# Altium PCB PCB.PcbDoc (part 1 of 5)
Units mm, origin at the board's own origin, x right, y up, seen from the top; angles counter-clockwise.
Board outline 101.6 x 53.34 mm, 6 copper layers (Top Layer, Int1 (GND), Int2, Int3, Int4 (GND), Bottom Layer), stack 1.625 mm thick; 228 components, 228 nets, 1016 pads, 995 vias.
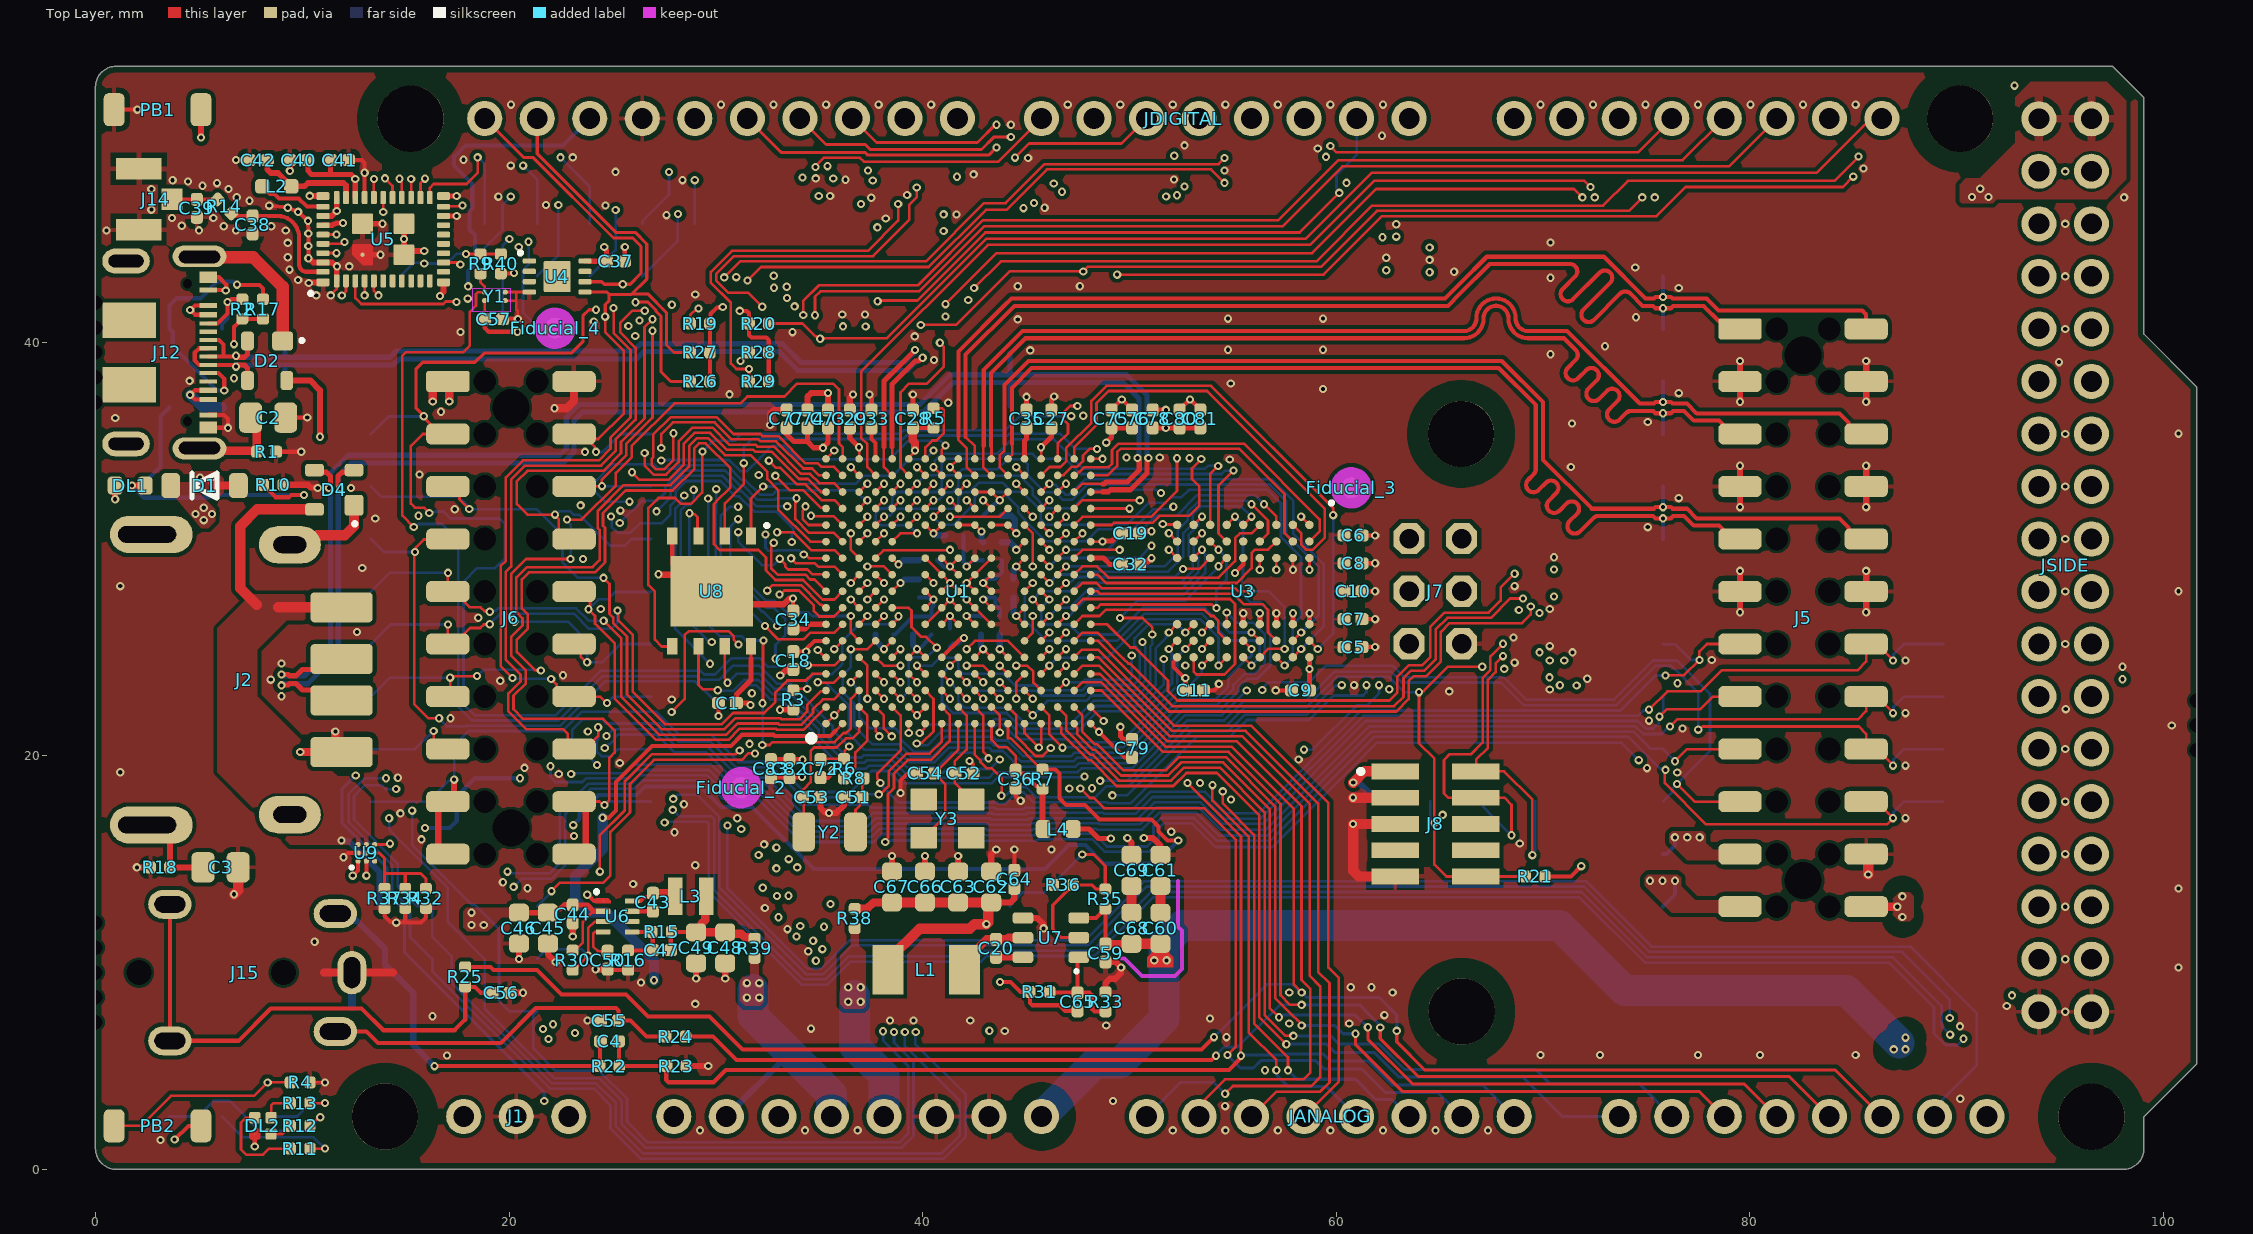
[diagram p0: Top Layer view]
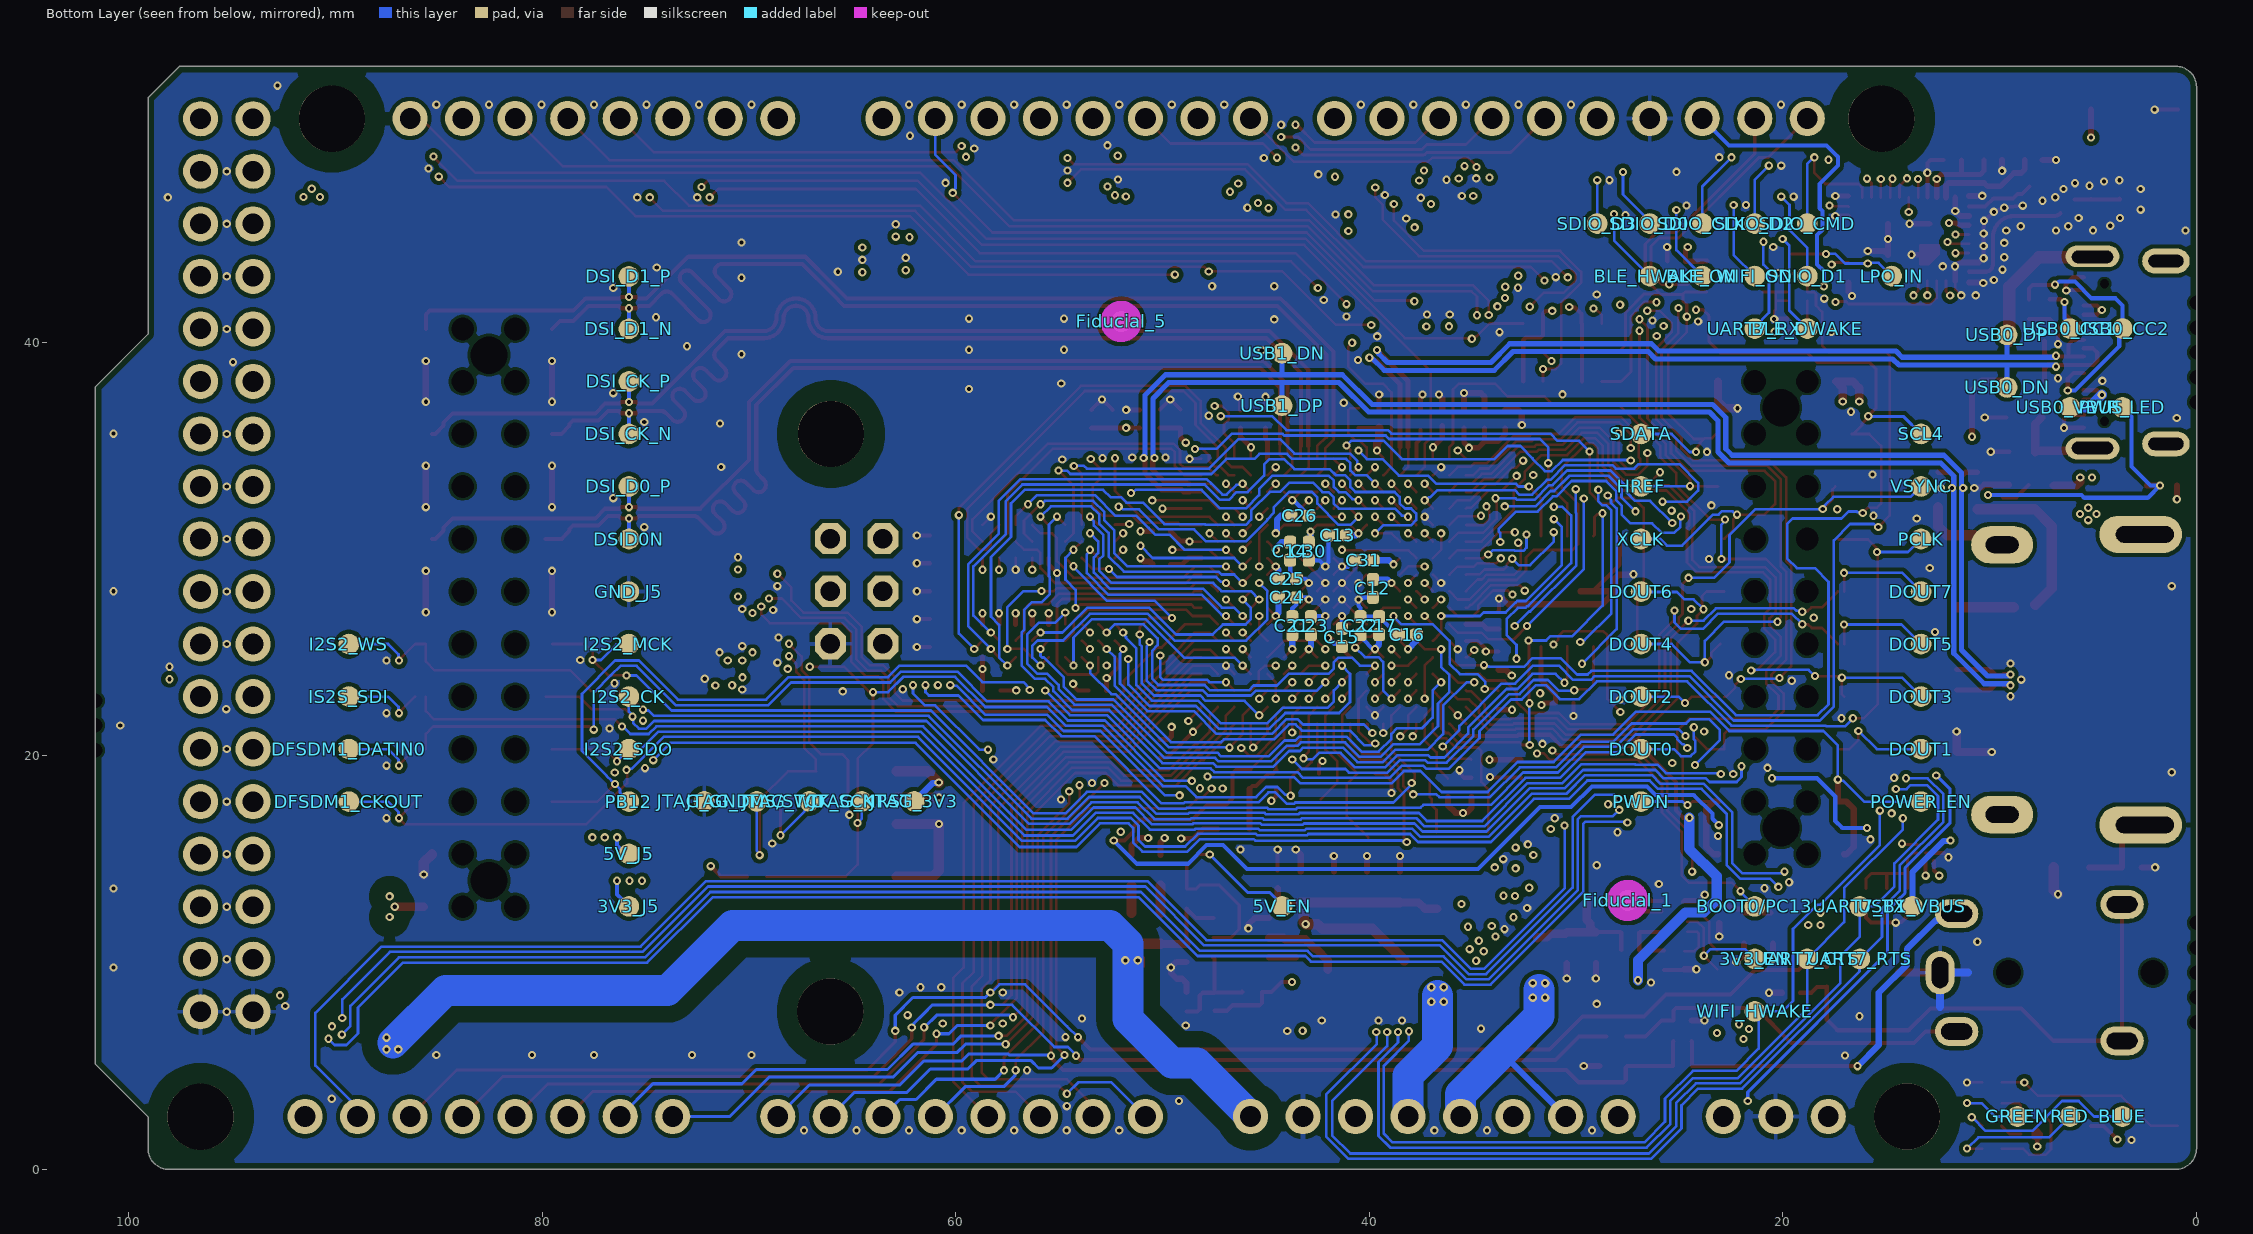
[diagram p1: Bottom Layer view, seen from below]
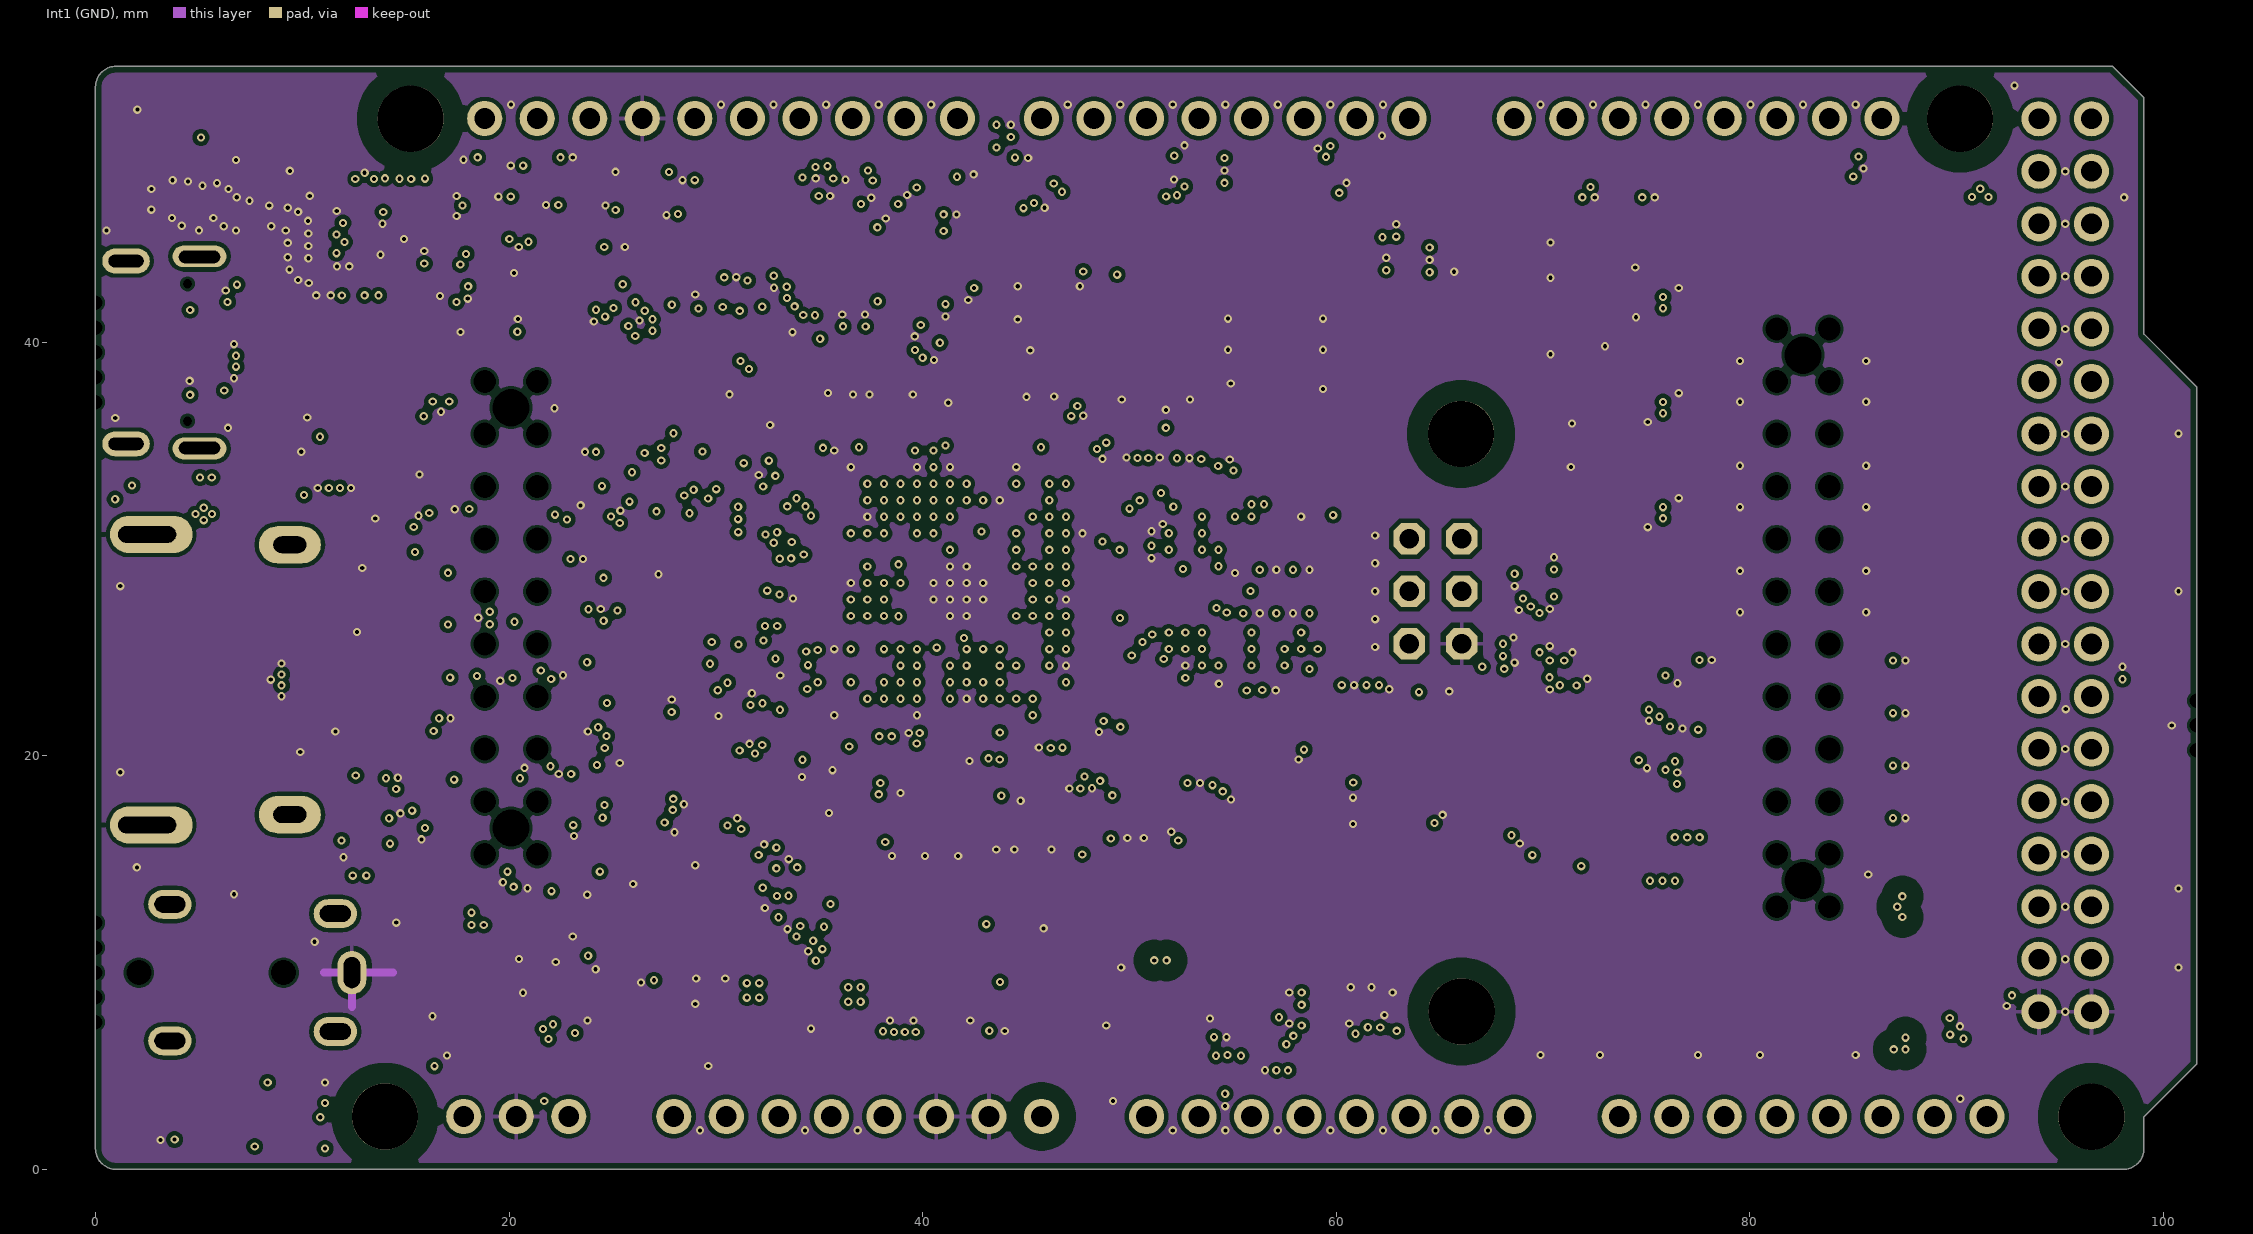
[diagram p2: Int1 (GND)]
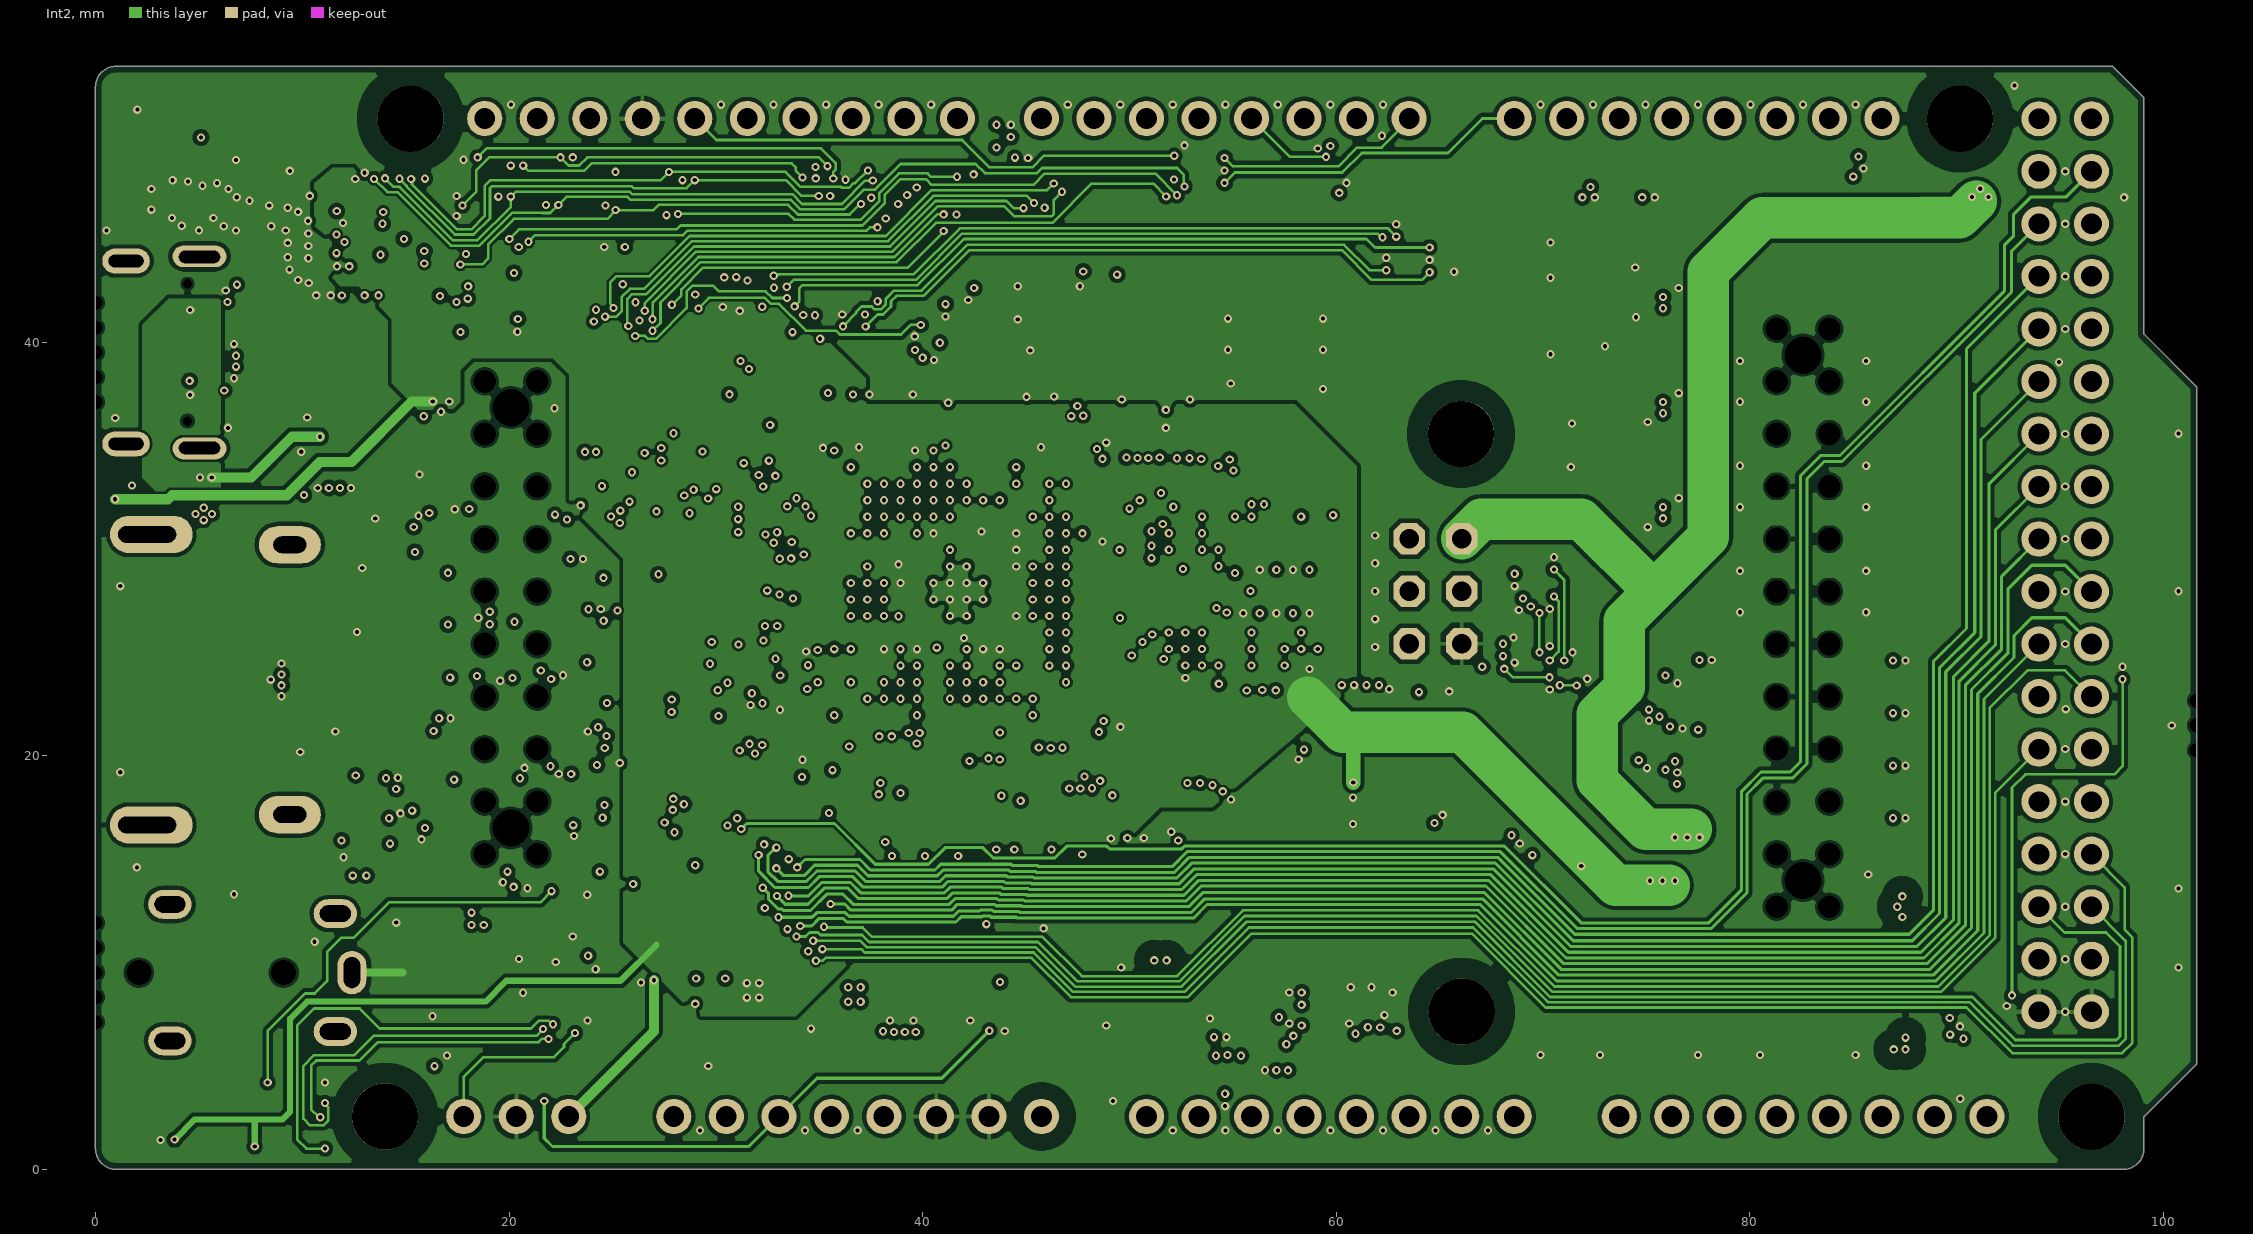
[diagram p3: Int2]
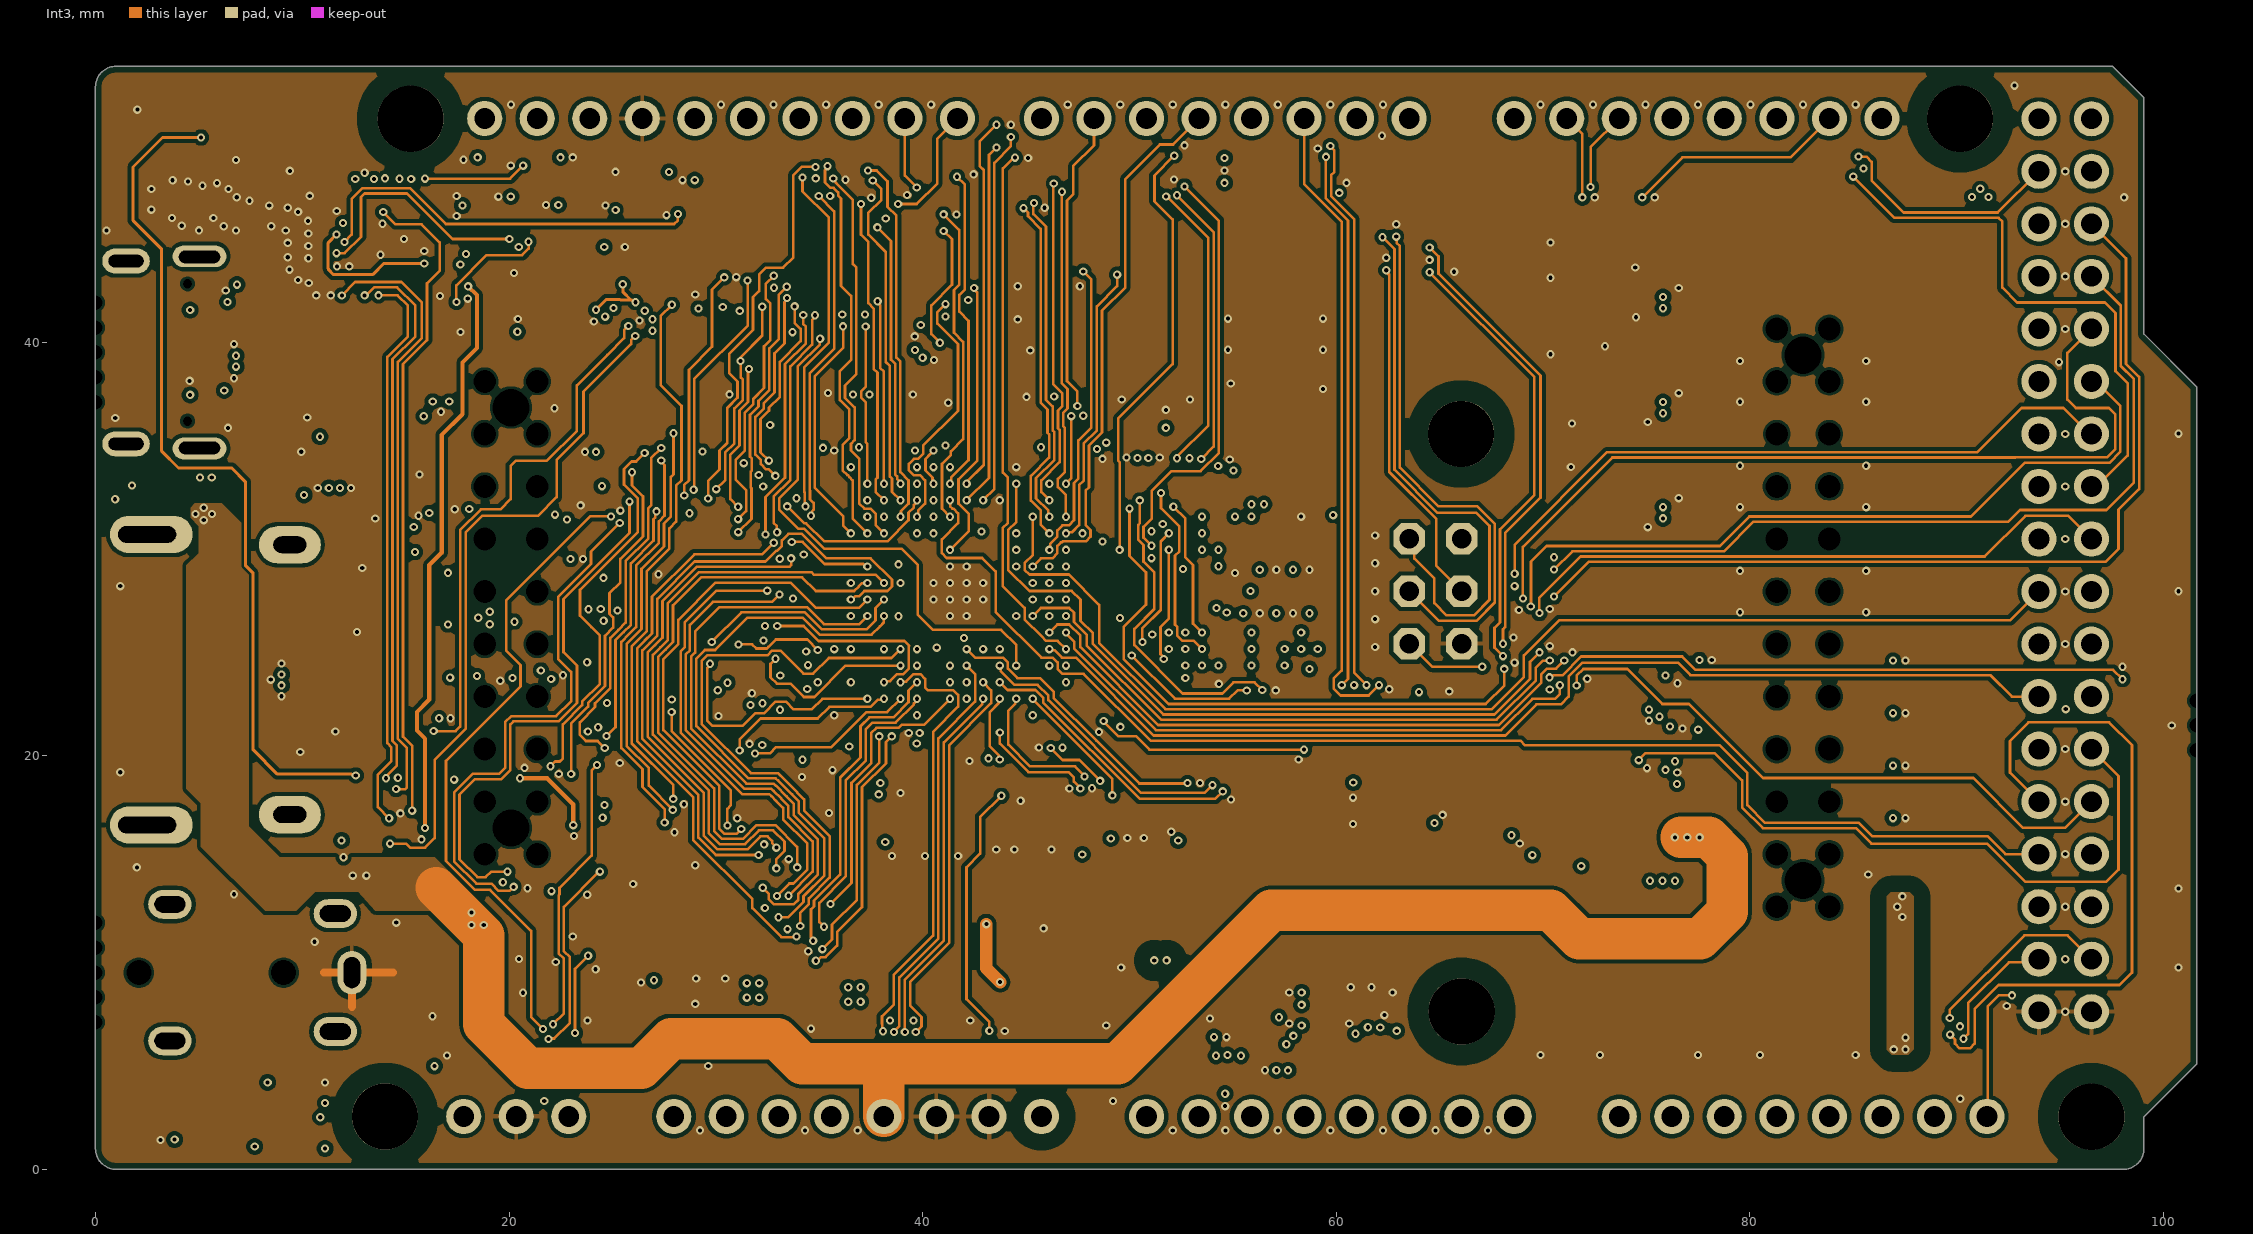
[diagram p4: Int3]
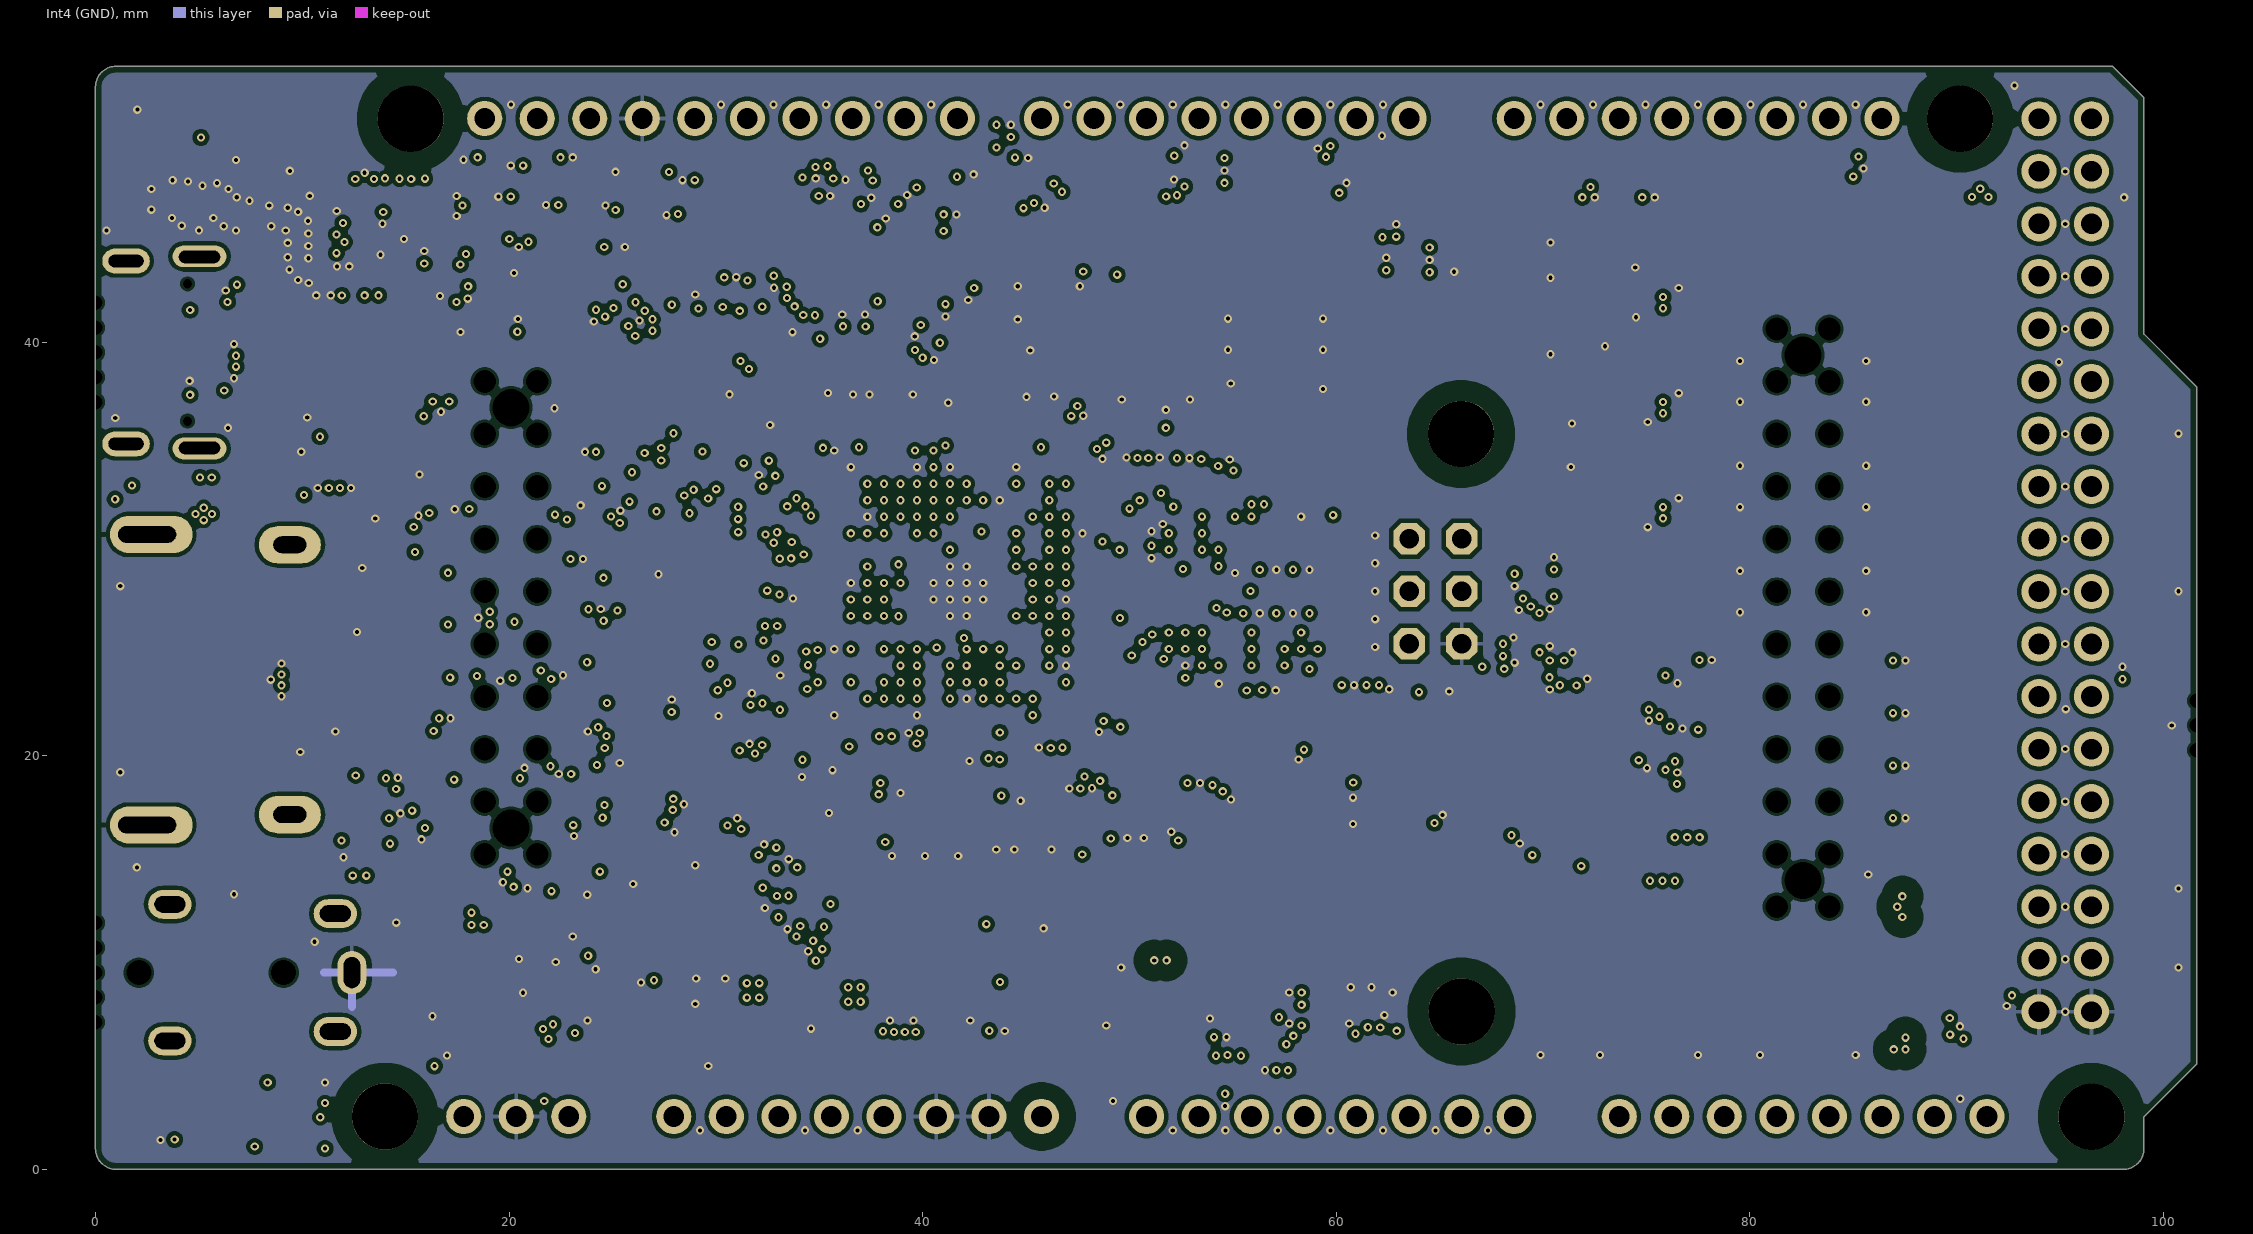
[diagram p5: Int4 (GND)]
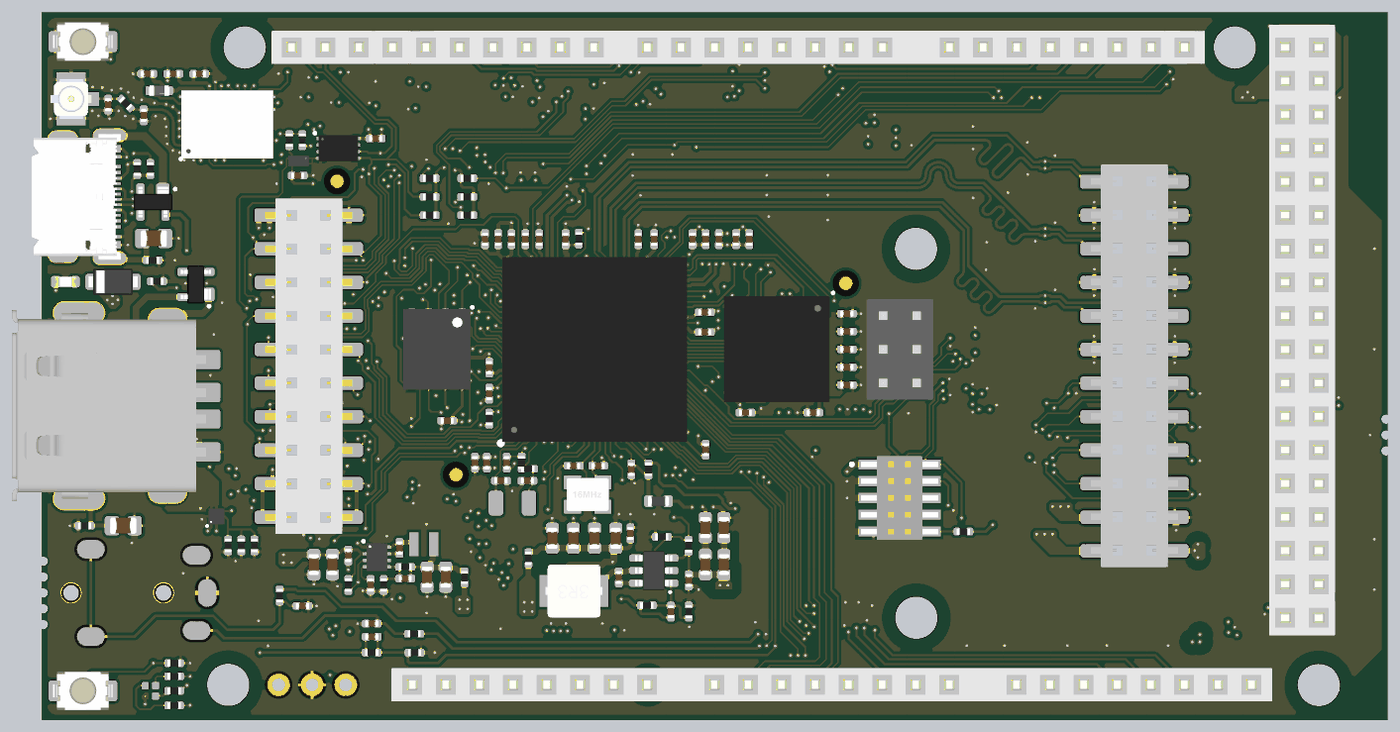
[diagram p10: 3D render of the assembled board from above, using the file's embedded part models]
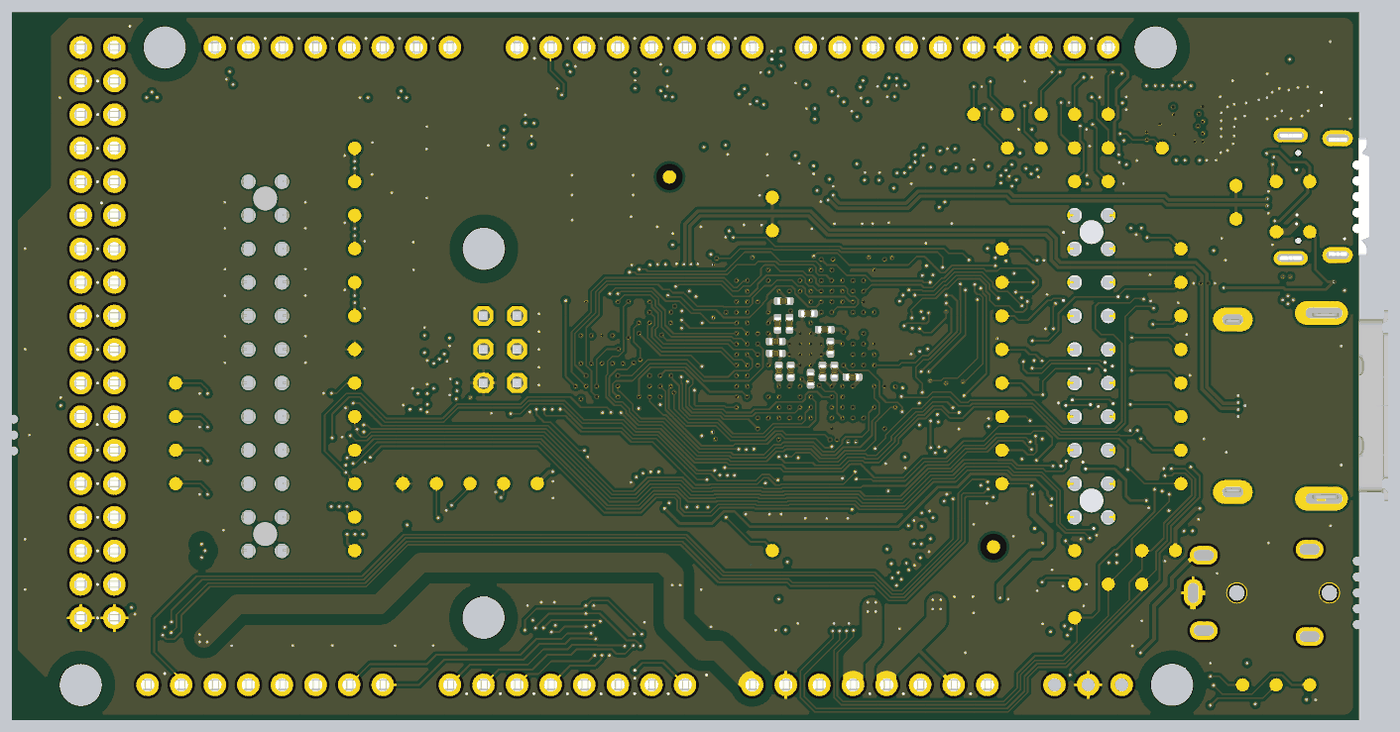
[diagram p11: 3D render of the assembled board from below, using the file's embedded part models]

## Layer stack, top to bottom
Top Solder: solder mask 0.0254, SM-003, Dk 4
Top Layer: signal copper 0.0175
Dielectric 1: prepreg 0.31, FR-4, Dk 4.3
Int1 (GND): signal copper 0.0175
Dielectric 2: core 0.33, PR1080, Dk 4.1
Int2: signal copper 0.0175
Dielectric 4: prepreg 0.24, FR-4, Dk 4.1
Int3: signal copper 0.0175
Dielectric 3: core 0.33, PR1080, Dk 4.1
Int4 (GND): signal copper 0.0175
Dielectric 5: prepreg 0.31, FR-4, Dk 4.3
Bottom Layer: signal copper 0.0175
Bottom Solder: solder mask 0.0254, SM-003, Dk 4

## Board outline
0,1 0,52.34 cw(c1,52.34) 1,53.34 97.536,53.34 99.06,51.816 99.06,40.386 101.6,37.846 101.6,5.08 99.06,2.54 99.06,1 cw(c98.06,1) 98.06,0 1,0 cw(c1,1)

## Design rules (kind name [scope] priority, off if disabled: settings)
BoardOutlineClearance MOUSEBITES [(ObjectKind = 'Pad') And (Name = 'Free-MOUSEBITE')] p1: gap=0 ignorepadtopadclearanceinfootprint=FALSE
BoardOutlineClearance Silks [(OnLayer('Top Overlay') OR OnLayer('Bottom Overlay'))] p2: gap=0 ignorepadtopadclearanceinfootprint=FALSE
BoardOutlineClearance [All] p3: gap=0.3 ignorepadtopadclearanceinfootprint=FALSE
Clearance mousebites_pol [All vs (ObjectKind = 'Pad') And (Name = 'Free-MOUSEBITE')] p1: gap=0.127 ignorepadtopadclearanceinfootprint=FALSE except(0.4: Arc-Fill Arc-Poly Arc-Region Track-Fill Track-Poly Track-Region SMDPad-Fill SMDPad-Poly SMDPad-Region THPad-Fill THPad-Poly THPad-Region Via-Fill Via-Poly Via-Region Fill-Fill Fill-Poly Fill-Region Poly-Poly Poly-Region Region-Region)
Clearance [(ObjectKind = 'Poly') And (Name = 'POWER_POLY')] p2: gap=0.5 ignorepadtopadclearanceinfootprint=TRUE
Clearance MH [(ObjectKind = 'Pad') And (Component = 'Free') And (Name = 'Free-MH')] p3: gap=1 ignorepadtopadclearanceinfootprint=FALSE
Clearance VIN40V_TOP [(InNet('VIN') AND OnLayer('Top Layer'))] p4: gap=0.2 ignorepadtopadclearanceinfootprint=TRUE
Clearance VIN40VnoPAD [(ObjectKind = 'Pad') And (Net = 'No Net') And (Component = 'J5') And (Name = 'J5-0') vs InNet('VIN')] p5: gap=0.127 ignorepadtopadclearanceinfootprint=TRUE
Clearance VIN40V [InNet('VIN')] p6: gap=0.25 ignorepadtopadclearanceinfootprint=TRUE except(0.15: Arc-SMDPad Track-SMDPad; 0.2: SMDPad-SMDPad; 0.6: SMDPad-Fill SMDPad-Poly SMDPad-Region; 0.8: Arc-Fill Arc-Poly Arc-Region Track-Fill Track-Poly Track-Region THPad-Fill THPad-Poly THPad-Region Via-Fill Via-Poly Via-Region Fill-Fill Fill-Poly Fill-Region Poly-Poly Poly-Region Region-Region)
Clearance GNDPOLYGONS [InNet('GND')] p7: gap=0.127 ignorepadtopadclearanceinfootprint=TRUE except(0.2: Arc-Fill Arc-Poly Arc-Region Track-Fill Track-Poly Track-Region SMDPad-Fill SMDPad-Poly SMDPad-Region THPad-Fill THPad-Poly THPad-Region Via-Fill Via-Poly Via-Region Fill-Fill Fill-Poly Fill-Region Poly-Poly Poly-Region Region-Region)
Clearance 3V3POLYGONS [(ObjectKind = 'Poly') And (Net = '+3V3')] p8: gap=0.3 ignorepadtopadclearanceinfootprint=FALSE
Clearance "Generic clearance 0.127mm" [All] p9: gap=0.127 ignorepadtopadclearanceinfootprint=FALSE
ComponentClearance Flash [HasFootprint('WSON8-1') vs HasFootprint('PSON127P600X60_HS-9N')] p1: gap=0 collisioncheckmode=3 verticalgap=0 showdistances=FALSE
ComponentClearance Fiducials [HasFootprint('Fiducial mark 1mm-Footprint-1')] p2: gap=0 collisioncheckmode=3 verticalgap=0.254 showdistances=FALSE
ComponentClearance 32k_R6R8 [InComponent('R6') vs InComponent('R8')] p3: gap=0 collisioncheckmode=3 verticalgap=0 showdistances=FALSE
ComponentClearance [All] p4: gap=0.2 collisioncheckmode=3 verticalgap=0 showdistances=TRUE
DiffPairsRouting [InDifferentialPairClass('DSI')] p1: maxlimit=2 minlimit=0.127 mostfreqgap=0.15 toplayer_minwidth=0.127 toplayer_maxwidth=0.2 toplayer_prefwidth=0.2 midlayer1_mingap=0.15 midlayer1_maxgap=0.15 midlayer1_minwidth=0.127 midlayer1_maxwidth=0.127 midlayer1_prefwidth=0.127 midlayer2_mingap=0.15 midlayer2_maxgap=0.15 midlayer2_minwidth=0.127 midlayer2_maxwidth=0.127 midlayer2_prefwidth=0.127 midlayer3_mingap=0.15 midlayer3_maxgap=0.15 midlayer3_minwidth=0.127 midlayer3_maxwidth=0.127 midlayer3_prefwidth=0.127 midlayer4_mingap=0.15 midlayer4_maxgap=0.15 midlayer4_minwidth=0.127 midlayer4_maxwidth=0.127 midlayer4_prefwidth=0.127 bottomlayer_maxgap=0.15 bottomlayer_minwidth=0.127 bottomlayer_maxwidth=0.2 bottomlayer_prefwidth=0.2 impedanceprofiledriven=TRUE impedanceprofileid={AD32D083-2DFB-4891-9FE5-643CC1F7C203} impedanceprofilevalue=100.000000 maxuncoupledlength=12.7
DiffPairsRouting USB [InDifferentialPairClass('USB')] p2: maxlimit=0.15 minlimit=0.127 mostfreqgap=0.15 toplayer_maxgap=0.127 toplayer_prefgap=0.127 toplayer_minwidth=0.127 toplayer_maxwidth=0.25 toplayer_prefwidth=0.25 midlayer1_minwidth=0.15 midlayer1_maxwidth=0.15 midlayer1_prefwidth=0.15 midlayer2_minwidth=0.15 midlayer2_maxwidth=0.15 midlayer2_prefwidth=0.15 midlayer3_minwidth=0.15 midlayer3_maxwidth=0.15 midlayer3_prefwidth=0.15 midlayer4_minwidth=0.15 midlayer4_maxwidth=0.15 midlayer4_prefwidth=0.15 bottomlayer_maxgap=0.127 bottomlayer_prefgap=0.127 bottomlayer_minwidth=0.127 bottomlayer_maxwidth=0.25 bottomlayer_prefwidth=0.25 impedanceprofiledriven=TRUE impedanceprofileid={586DF874-F34C-49A6-9A09-DEFA45723978} impedanceprofilevalue=90.000000 maxuncoupledlength=12.7
Height [All] p1: minheight=0 maxheight=30 prefheight=12.7
HoleSize [All] p1: absolutevalues=TRUE maxlimit=20 minlimit=0.2 maxpercent=80.000 minpercent=20.000
HoleToHoleClearance HoleToHoleClearance_1 [HasFootprint('CX90B1-24P') vs HasFootprint('CX90B1-24P')] p1: gap=0 allowstackedmicrovias=TRUE
HoleToHoleClearance [All] p2: gap=0.25 allowstackedmicrovias=FALSE
MatchedLengths MatchedLengths_1 [InDifferentialPairClass('DSI')] p1: tolerance=25.4 checknetsindiffpair=TRUE checkdiffpairvsdiffpair=FALSE checkxsignals=FALSE checkothers=FALSE usedelayunits=TRUE delaytolerance=12.000000
MatchedLengths [InDifferentialPairClass('DSI')] p2: tolerance=25.4 checknetsindiffpair=FALSE checkdiffpairvsdiffpair=TRUE checkxsignals=TRUE checkothers=TRUE usedelayunits=TRUE delaytolerance=25.000000
PlaneConnect [All] p1: pad.planeconnectstyle=Relief pad.reliefexpansion=0.508 pad.reliefentries=4 pad.reliefconductorwidth=0.254 pad.reliefairgap=0.254 via.planeconnectstyle=Direct via.reliefexpansion=0.508 via.reliefentries=4 via.reliefconductorwidth=0.254 via.reliefairgap=0.254
PolygonConnect 3V3_FLASH [All vs (ObjectKind = 'Poly') And (Net = '+3V3') And (Name = '+3V3_FLASH')] p1: thpad.connectstyle=Direct thpad.reliefconductorwidth=0.254 thpad.reliefentries=4 thpad.polygonreliefangle="90 Angle" thpad.airgapwidth=0.254 smdpad.connectstyle=Relief smdpad.reliefconductorwidth=0.15 smdpad.reliefentries=4 smdpad.polygonreliefangle="90 Angle" smdpad.airgapwidth=0.15 via.connectstyle=Direct via.reliefconductorwidth=0.254 via.reliefentries=4 via.polygonreliefangle="90 Angle" via.airgapwidth=0.254
PolygonConnect 5VTOP [InNet('+5V')] p2: thpad.connectstyle=Relief thpad.reliefconductorwidth=0.4 thpad.reliefentries=4 thpad.polygonreliefangle="90 Angle" thpad.airgapwidth=0.254 smdpad.connectstyle=Direct smdpad.reliefconductorwidth=0.254 smdpad.reliefentries=4 smdpad.polygonreliefangle="90 Angle" smdpad.airgapwidth=0.254 via.connectstyle=Direct via.reliefconductorwidth=0.254 via.reliefentries=4 via.polygonreliefangle="90 Angle" via.airgapwidth=0.254
PolygonConnect 3V3TOP [InNet('+3V3')] p3: thpad.connectstyle=Relief thpad.reliefconductorwidth=0.4 thpad.reliefentries=4 thpad.polygonreliefangle="90 Angle" thpad.airgapwidth=0.254 smdpad.connectstyle=Direct smdpad.reliefconductorwidth=0.254 smdpad.reliefentries=4 smdpad.polygonreliefangle="90 Angle" smdpad.airgapwidth=0.254 via.connectstyle=Direct via.reliefconductorwidth=0.254 via.reliefentries=4 via.polygonreliefangle="90 Angle" via.airgapwidth=0.254
PolygonConnect [All] p4: thpad.connectstyle=Relief thpad.reliefconductorwidth=0.2 thpad.reliefentries=4 thpad.polygonreliefangle="90 Angle" thpad.airgapwidth=0.254 smdpad.connectstyle=Relief smdpad.reliefconductorwidth=0.2 smdpad.reliefentries=4 smdpad.polygonreliefangle="90 Angle" smdpad.airgapwidth=0.254 via.connectstyle=Direct via.reliefconductorwidth=0.254 via.reliefentries=4 via.polygonreliefangle="90 Angle" via.airgapwidth=0.254
RoomDefinition STM32H747 [InComponentClass('STM32H747')] p1: confinementstyle=ConfineIn formatcopy=TRUE lockcomponents=FALSE outline -40.4,-40.4 10.4,-40.4 10.4,-15 -40.4,-15
RoomDefinition HEADERS [InComponentClass('HEADERS')] p2: confinementstyle=ConfineIn formatcopy=TRUE lockcomponents=FALSE outline 101.84,2.78 109.46,2.78 109.46,15.48 101.84,15.48
RoomDefinition CRYPTOCHIP [InComponentClass('CRYPTOCHIP')] p3: confinementstyle=ConfineIn formatcopy=TRUE lockcomponents=FALSE outline -40.4,-40.4 10.4,-40.4 10.4,-15 -40.4,-15
RoomDefinition U_USB [InComponentClass('U_USB')] p4: confinementstyle=ConfineIn formatcopy=TRUE lockcomponents=FALSE outline -40.4,-40.4 10.4,-40.4 10.4,-15 -40.4,-15
RoomDefinition WIFI [InComponentClass('WIFI')] p5: confinementstyle=ConfineIn formatcopy=TRUE lockcomponents=FALSE outline -40.4,-40.4 10.4,-40.4 10.4,-15 -40.4,-15
RoomDefinition U_AUDIO [InComponentClass('U_AUDIO')] p6: confinementstyle=ConfineIn formatcopy=TRUE lockcomponents=FALSE outline -40.4,-40.4 10.4,-40.4 10.4,-15 -40.4,-15
RoomDefinition U_POWER [InComponentClass('U_POWER')] p7: confinementstyle=ConfineIn formatcopy=TRUE lockcomponents=FALSE outline 57.6,-10.4 61.6,-10.4 61.6,-6.4 57.6,-6.4
RoomDefinition TOP [InComponentClass('TOP')] p8: confinementstyle=ConfineIn formatcopy=TRUE lockcomponents=FALSE outline 102.7,1.5 112.4,1.5 112.4,12.5 102.7,12.5
RoutingVias TOPBOTTOM [InDrillLayerPair('Top Layer - Bottom Layer')] p1: holewidth=0.2 width=0.4 viastyle="Through Hole" minholewidth=0.2 minwidth=0.4 maxholewidth=0.2 maxwidth=0.4
ShortCircuit ShortCircuit_1 [(ObjectKind = 'Pad') And (Name = 'J12-FIXING') vs (ObjectKind = 'Pad') And (Name = 'Free-MOUSEBITE')] p1: allowed=TRUE
ShortCircuit [All] p2: allowed=FALSE
SilkToSilkClearance [All] p1: silktosilkclearance=0.2
SilkToSolderMaskClearance [IsPad] p1: minsilkscreentomaskgap=0.15 clearancetoexposedcopper=TRUE
SolderMaskExpansion VIAtented [IsVia] p1: expansion=0.102 istentingtop=TRUE
SolderMaskExpansion [All] p2: expansion=0.05 istentingtop=FALSE
UnRoutedNet [All] p1: checkbadconnections=TRUE
ViasUnderSMD [All] p1: allowed=FALSE
Width 50ohm [InNetClass('50 ohm')] p1: maxlimit=0.254 minlimit=0.2 preferedwidth=0.254 toplayer_maxwidth=0.2 toplayer_prefwidth=0.2 bottomlayer_maxwidth=0.2 bottomlayer_prefwidth=0.2 impedanceprofiledriven=TRUE impedanceprofileid={CBBC4A3A-112E-4A5A-AB75-891062E67277} impedanceprofilevalue=50.000000 minimp=50.000000 maximp=50.000000 favimp=50.000000
Width StandardTraces [All] p2: maxlimit=5 minlimit=0.127 preferedwidth=0.15
20 further rules are at their usual default settings.

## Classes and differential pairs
net class GND: GND
net class LTDC: PE6 PG10 PG12 PG13 PH15 PI10 PI11 PI13 PI14 PI15 PJ0 PJ1 PJ2 PJ3 PJ4 PJ5 PJ6 PJ7 PJ12 PJ14 PJ15 PK0 PK2 PK3 PK4 PK5 PK6 PK7
net class FLASH: PD11_5 PD12_5 PE2_5 PF6_5 PF10_5 PG6_5
net class ANALOG: LEFT MIC PA0_C PA1_C PA4 PB0 PB1 PC0 PC2 PC2_C PC3 PC3_C PC4 PC5
net class RAM: PD0_5 PD1_5 PD8_5 PD9_5 PD10_5 PD14_5 PD15_5 PE0_5 PE1_5 PE7_5 PE8_5 PE9_5 PE10_5 PE11_5 PE12_5 PE13_5 PE14_5 PE15_5 PF0_5 PF1_5 PF2_5 PF3_5 PF4_5 PF5_5 PF11_5 PF12_5 PF13_5 PF14_5 PF15_5 PG0_5 PG1_5 PG2_5 PG4_5 PG5_5 PG8_5 PG15_5 PH2_5 PH3_5 PH5_5
differential pair class DSI: DSI_CK DSI_D0 DSI_D1
differential pair class USB: USB0_D USB1_D
component class U_USB: C2 C3 D1 D2 D4 J2 J12 R1 R2 R17 R18 R32 R34 R37 U9 USB0_CC1 USB0_CC2 USB0_DN USB0_DP USB0_VBUS USB1_DN USB1_DP USB1_VBUS
component class STM32H747: C1 C5 C6 C7 C8 C9 C10 C11 C12 C13 C14 C15 C16 C17 C18 C19 C21 C22 C23 C24 C25 C26 C27 C28 C29 C30 C31 C32 C33 C34 C35 C36 C51 C52 C53 C54 C57 C72 C73 C74 C75 C76 C77 C78 C79 C80 C81 C82 C83 L4 R3 R4 R5 R6 R7 R8 R19 R20 R21 R26 R27 R28 R29 U1 U3 U8 Y1 Y2 Y3
component class U_POWER: 3V3_EN 5V_EN C20 C43 C44 C45 C46 C47 C48 C49 C50 C59 C60 C61 C62 C63 C64 C65 C66 C67 C68 C69 L1 L3 R15 R16 R30 R31 R33 R35 R36 R38 R39 U6 U7
component class HEADERS: 3V3_J5 5V_J5 DFSDM1_CKOUT DFSDM1_DATIN0 DOUT0 DOUT1 DOUT2 DOUT3 DOUT4 DOUT5 DOUT6 DOUT7 DSI_CK_N DSI_CK_P DSI_D0_P DSI_D1_N DSI_D1_P DSID0N GND_J5 HREF I2S2_CK I2S2_MCK I2S2_SDO I2S2_WS IS2S_SDI J1 J5 J6 J7 J8 JANALOG JDIGITAL JSIDE JTAG_3V3 JTAG_GND JTAG_NRST JTAG_TCK_SCK JTAG_TMS/SWD PB12 PCLK POWER_EN PWDN SCL4 SDATA VSYNC XCLK
component class U_AUDIO: C4 C55 C56 J15 R22 R23 R24 R25
component class CRYPTOCHIP: C37 U4
net class "50 ohm": NetC38_1 NetC39_1
component class WIFI: BLE_DWAKE BLE_HWAKE BLE_ON C38 C39 C40 C41 C42 J14 L2 LPO_IN R9 R14 R40 SDIO_CLK SDIO_CMD SDIO_D0 SDIO_D1 SDIO_D2 SDIO_D3 U5 UART7_CTS UART7_RTS UART7_RX UART7_TX WIFI_HWAKE WIFI_ON
component class TOP: BLUE BOOT0/PC13 DL1 DL2 Fiducial_1 Fiducial_2 Fiducial_3 Fiducial_4 Fiducial_5 GREEN PB1 PB2 PWR_LED R10 R11 R12 R13 RED
differential pair DSI_D1: +DSI_D1_P -DSI_D1_N
differential pair DSI_D0: +DSI_D0_P -DSI_D0_N
differential pair DSI_CK: +DSI_CK_P -DSI_CK_N
differential pair USB1_D: +USB1_D_P -USB1_D_N
differential pair USB0_D: +USB0_D_P -USB0_D_N

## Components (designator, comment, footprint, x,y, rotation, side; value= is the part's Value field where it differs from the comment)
3V3_EN "CMP-018-0005-A.3" TP-1.00MM 21.362,10.173 r180 bottom
3V3_J5 "CMP-018-0005-A.3" TP-1.00MM 75.805,12.713 r180 bottom
5V_EN "CMP-018-0005-A.3" TP-1.00MM 44.222,12.713 r180 bottom
5V_J5 "CMP-018-0005-A.3" TP-1.00MM 75.805,15.253 r90 bottom
BLE_DWAKE "CMP-018-0005-A.3" TP-1.00MM 18.822,40.653 r180 bottom
BLE_HWAKE "CMP-018-0005-A.3" TP-1.00MM 26.442,43.193 r180 bottom
BLE_ON "CMP-018-0005-A.3" TP-1.00MM 23.902,43.193 r180 bottom
BLUE "CMP-018-0005-A.3" TP-1.00MM 3.582,2.553 r270 bottom
BOOT0/PC13 "CMP-018-0005-A.3" TP-1.00MM 21.362,12.713 r180 bottom
C1 "GRM155R61H104KE19D" CAP-0402#1 30.566,22.548 r0 top value=100nF
C2 "FV21X472K102ECG" CAP-0805 8.35,36.35 r180 top value=4.7nF
C3 "FV21X472K102ECG" CAP-0805 6.05,14.6 r180 top value=4.7nF
C4 "DNP CAP 0402" CAP-0402#1 24.855,6.19 r0 top
C5 "GRM155R61H104KE19D" CAP-0402#1 60.813,25.253 r180 top value=100nF
C6 "GRM155R61H104KE19D" CAP-0402#1 60.813,30.653 r180 top value=100nF
C7 "GRM155R61H104KE19D" CAP-0402#1 60.813,26.603 r180 top value=100nF
C8 "GRM155R61H104KE19D" CAP-0402#1 60.813,29.303 r180 top value=100nF
C9 "GRM155R61H104KE19D" CAP-0402#1 58.269,23.16 r0 top value=100nF
C10 "GRM155R61H104KE19D" CAP-0402#1 60.813,27.953 r180 top value=100nF
C11 "GRM155R61H104KE19D" CAP-0402#1 53.139,23.16 r180 top value=100nF
C12 "GRM155R60J106ME05D" CAP-0402#2 39.826,28.088 r90 bottom value=10µF
C13 "GRM155R60J225KE95D" CAP-0402#2 41.539,30.66 r180 bottom value=2.2µF
C14 "GRM155R60J225KE95D" CAP-0402#2 43.826,29.888 r90 bottom value=2.2µF
C15 "GRM155R60J225KE95D" CAP-0402#2 41.326,25.718 r270 bottom value=2.2µF
C16 "GRM155R61H104KE19D" CAP-0402#2 38.161,25.853 r180 bottom value=100nF
C17 "GRM155R61H104KE19D" CAP-0402#2 39.526,26.288 r270 bottom value=100nF
C18 "GRM155R61H104KE19D" CAP-0402#1 33.746,24.598 r90 top value=100nF
C19 "GRM155R61H104KE19D" CAP-0402#1 50.056,30.753 r180 top value=100nF
C20 "GRM155R61H104KE19D" CAP-0402#1 43.55,10.685 r90 top value=100nF
C21 "GRM155R61H104KE19D" CAP-0402#2 43.726,26.288 r270 bottom value=100nF
C22 "GRM155R61H104KE19D" CAP-0402#2 40.426,26.288 r270 bottom value=100nF
C23 "GRM155R61H104KE19D" CAP-0402#2 42.826,26.288 r270 bottom value=100nF
C24 "GRM155R61H104KE19D" CAP-0402#2 43.961,27.653 r0 bottom value=100nF
C25 "GRM155R61H104KE19D" CAP-0402#2 43.961,28.553 r0 bottom value=100nF
C26 "GRM155R61H104KE19D" CAP-0402#2 43.361,31.603 r0 bottom value=100nF
C27 "GRM155R61H104KE19D" CAP-0402#1 46.226,36.288 r270 top value=100nF
C28 "GRM155R61H104KE19D" CAP-0402#1 39.526,36.288 r270 top value=100nF
C29 "GRM155R61H104KE19D" CAP-0402#1 36.476,36.288 r270 top value=100nF
C30 "GRM155R61H104KE19D" CAP-0402#2 42.926,29.888 r90 bottom value=100nF
C31 "GRM155R61H104KE19D" CAP-0402#2 40.261,29.453 r180 bottom value=100nF
C32 "GRM155R60J225KE95D" CAP-0402#1 50.056,29.253 r180 top value=2.2µF
C33 "GRM155R60J225KE95D" CAP-0402#1 37.526,36.288 r270 top value=2.2µF
C34 "GRM155R60J225KE95D" CAP-0402#1 33.746,26.568 r270 top value=2.2µF
C35 "GRM155R60J225KE95D" CAP-0402#1 45.026,36.288 r270 top value=2.2µF
C36 "GRM155R60J106ME05D" CAP-0402#1 44.5,18.865 r90 top value=10µF
C37 "GRM155R61H104KE19D" CAP-0402#1 25.152,43.909 r180 top value=100nF
C38 "CAP-0402-DNP" CAP-0402#1 7.6,45.665 r270 top
C39 "CAP-0402-DNP" CAP-0402#1 4.903,46.469 r270 top
C40 "GRM155R60J225KE95D" CAP-0402#1 9.835,48.804 r0 top value=2.2µF
C41 "C1005A475M6R3NT" CAP-0402#1 11.805,48.804 r0 top value=4.7µF
C42 "C1005A475M6R3NT" CAP-0402#1 7.873,48.804 r180 top value=4.7µF
C43 "GRM155R61H104KE19D" CAP-0402#1 26.957,12.914 r270 top value=100nF
C44 "GRM155R61H104KE19D" CAP-0402#1 23.078,12.344 r270 top value=100nF
C45 "C1608A106M250NT" CAP-0603 21.878,11.659 r90 top value=10µF
C46 "C1608A106M250NT" CAP-0603 20.478,11.659 r90 top value=10µF
C47 "0402N220J500CT" CAP-0402#1 27.382,10.599 r0 top value=22pF
C48 "C1608A106M250NT" CAP-0603 30.451,10.712 r90 top value=10µF
C49 "C1608A106M250NT" CAP-0603 29.045,10.712 r90 top value=10µF
C50 "GRM155R60J225KE95D" CAP-0402#1 24.768,10.111 r90 top value=2.2µF
C51 "C0402C180J5GACTU" CAP-0402#1 36.635,18 r180 top value=18pF
C52 "C0402H100J5GACTU" CAP-0402#1 41.991,19.143 r0 top value=10pF
C53 "C0402C180J5GACTU" CAP-0402#1 34.63,18 r0 top value=18pF
C54 "C0402H100J5GACTU" CAP-0402#1 40.126,19.143 r180 top value=10pF
C55 "DNP CAP 0402" CAP-0402#1 24.855,7.19 r0 top
C56 "DNP CAP 0402" CAP-0402#1 19.613,8.534 r180 top
C57 "GRM155R61H104KE19D" CAP-0402#1 19.254,41.11 r180 top value=100nF
C59 "GRM155R61H104KE19D" CAP-0402#1 48.842,10.459 r270 top value=100nF
C60 "C1608A106M250NT" CAP-0603 51.5,11.653 r270 top value=10µF
C61 "C1608A106M250NT" CAP-0603 51.5,14.453 r270 top value=10µF
C62 "C1608A106M250NT" CAP-0603 43.316,13.653 r270 top value=10µF
C63 "C1608A106M250NT" CAP-0603 41.716,13.653 r270 top value=10µF
C64 "GRM155R61H104KE19D" CAP-0402#1 44.433,14.022 r90 top value=100nF
C65 "CC0402JRNPO9BN101" CAP-0402#1 47.492,8.1 r270 top value=100pF
C66 "C1608A106M250NT" CAP-0603 40.116,13.653 r270 top value=10µF
C67 "C1608A106M250NT" CAP-0603 38.516,13.653 r270 top value=10µF
C68 "C1608A106M250NT" CAP-0603 50.1,11.653 r270 top value=10µF
C69 "C1608A106M250NT" CAP-0603 50.1,14.453 r270 top value=10µF
C72 "CAP-0402-DNP" CAP-0402#1 35.065,19.37 r270 top
C73 "GRM155R60J106ME05D" CAP-0402#1 35.426,36.288 r270 top value=10µF
C74 "GRM155R60J106ME05D" CAP-0402#1 34.426,36.288 r270 top value=10µF
C75 "GRM155R60J106ME05D" CAP-0402#1 49.126,36.288 r270 top value=10µF
C76 "GRM155R60J106ME05D" CAP-0402#1 50.126,36.288 r270 top value=10µF
C77 "GRM155R61H104KE19D" CAP-0402#1 33.426,36.288 r270 top value=100nF
C78 "GRM155R61H104KE19D" CAP-0402#1 51.126,36.288 r270 top value=100nF
C79 "GRM155R61H104KE19D" CAP-0402#1 50.126,20.353 r90 top value=100nF
C80 "GRM155R60J106ME05D" CAP-0402#1 52.426,36.288 r270 top value=10µF
C81 "GRM155R60J106ME05D" CAP-0402#1 53.426,36.288 r270 top value=10µF
C82 "GRM155R60J106ME05D" CAP-0402#1 33.565,19.37 r90 top value=10µF
C83 "GRM155R61H104KE19D" CAP-0402#1 32.665,19.37 r90 top value=100nF
D1 "PMEG6020AELRX" SOD123-1 5.275,33.062 r0 top
D2 "PRTR5V0U2X,215" SOT190P230X110-4N 8.3,39.1 r180 top
D4 "PRTR5V0U2X,215" SOT190P230X110-4N 11.546,32.86 r90 top
DFSDM1_CKOUT "CMP-018-0005-A.3" TP-1.00MM 89.345,17.779 r180 bottom
DFSDM1_DATIN0 "CMP-018-0005-A.3" TP-1.00MM 89.345,20.319 r180 bottom
DL1 "HSMG-C190" LEDC1608X80N-AK 1.675,33.062 r180 top
DL2 "UHD1110-FKA-CL1A13R3Q1BBQFMF3" UHD1110-FKA-CL1A13R3Q1BBQFMF3 8.1,2.1 r90 top
DOUT0 "CMP-018-0005-A.3" TP-1.00MM 26.862,20.319 r180 bottom
DOUT1 "CMP-018-0005-A.3" TP-1.00MM 13.322,20.319 r180 bottom
DOUT2 "CMP-018-0005-A.3" TP-1.00MM 26.862,22.859 r180 bottom
DOUT3 "CMP-018-0005-A.3" TP-1.00MM 13.322,22.859 r180 bottom
DOUT4 "CMP-018-0005-A.3" TP-1.00MM 26.862,25.399 r180 bottom
DOUT5 "CMP-018-0005-A.3" TP-1.00MM 13.322,25.399 r180 bottom
DOUT6 "CMP-018-0005-A.3" TP-1.00MM 26.862,27.939 r180 bottom
DOUT7 "CMP-018-0005-A.3" TP-1.00MM 13.322,27.939 r180 bottom
DSI_CK_N "CMP-018-0005-A.3" TP-1.00MM 75.805,35.559 r90 bottom
DSI_CK_P "CMP-018-0005-A.3" TP-1.00MM 75.805,38.099 r90 bottom
DSI_D0_P "CMP-018-0005-A.3" TP-1.00MM 75.805,33.019 r180 bottom
DSI_D1_N "CMP-018-0005-A.3" TP-1.00MM 75.805,40.639 r180 bottom
DSI_D1_P "CMP-018-0005-A.3" TP-1.00MM 75.805,43.179 r180 bottom
DSID0N "CMP-018-0005-A.3" TP-1.00MM 75.805,30.479 r180 bottom
Fiducial_1 "Fiducial mark 1mm" "Fiducial mark 1mm-Footprint-1" 27.5,13 r90 bottom
Fiducial_2 "Fiducial mark 1mm" "Fiducial mark 1mm-Footprint-1" 31.226,18.453 r90 top
Fiducial_3 "Fiducial mark 1mm" "Fiducial mark 1mm-Footprint-1" 60.726,32.953 r90 top
Fiducial_4 "Fiducial mark 1mm" "Fiducial mark 1mm-Footprint-1" 22.226,40.67 r90 top
Fiducial_5 "Fiducial mark 1mm" "Fiducial mark 1mm-Footprint-1" 52,41 r90 bottom
GND_J5 "CMP-018-0005-A.3" TP-1.00MM 75.805,27.939 r180 bottom
GREEN "CMP-018-0005-A.3" TP-1.00MM 8.662,2.553 r180 bottom
HREF "CMP-018-0005-A.3" TP-1.00MM 26.862,33.019 r180 bottom
I2S2_CK "CMP-018-0005-A.3" TP-1.00MM 75.805,22.859 r180 bottom
I2S2_MCK "CMP-018-0005-A.3" TP-1.00MM 75.805,25.399 r180 bottom
I2S2_SDO "CMP-018-0005-A.3" TP-1.00MM 75.805,20.319 r180 bottom
I2S2_WS "CMP-018-0005-A.3" TP-1.00MM 89.345,25.399 r180 bottom
IS2S_SDI "CMP-018-0005-A.3" TP-1.00MM 89.345,22.859 r180 bottom
J1 "HEADER TH 2.54mm VERT. 1x003POS" "PIN HEADER 2.54mm VERT. 1x3POS" 20.346,2.553 r0 top
J2 "USB-A-S-RA-CS11-SMT-HF-TR" USB-A-S-RA-CS11-SMT-HF-TR 5.9,23.675 r270 top locked
J5 "21TW-291" 21TW-291 82.575,26.669 r270 top locked
J6 "21TW-247" 21TW-247 20.092,26.669 r270 top
J7 "PH2-06-UA" 2X03 64.796,27.953 r90 top
J8 "22TW-428" FTSH-105-01-F-DV-Footprint-1 64.796,16.7 r270 top
J12 "CX90B-16P" CX90B-16P-Footprint-1 3.467,39.5 r270 top locked
J14 "U.FL-R-SMT-1(60)" U.FL-R-SMT-1(60)-1 2.103,46.904 r90 top
J15 "22TW-258" 22TW-258-Footprint-1 6.25,9.513 r0 top locked
JANALOG "20TW-887" "GIGA header custom analog" 58.446,2.553 r0 top locked
JDIGITAL "20TW-890" "GIGA Header custom digital" 53.366,50.813 r0 top locked
JSIDE "20TW-891" "GIGA custom header side-Footprint-1" 95.25,29.209 r0 top locked
JTAG_3V3 "CMP-018-0005-A.3" TP-1.00MM 62.002,17.793 r180 bottom
JTAG_GND "CMP-018-0005-A.3" TP-1.00MM 72.162,17.793 r180 bottom
JTAG_NRST "CMP-018-0005-A.3" TP-1.00MM 64.542,17.793 r180 bottom
JTAG_TCK_SCK "CMP-018-0005-A.3" TP-1.00MM 67.082,17.793 r180 bottom
JTAG_TMS/SWD "CMP-018-0005-A.3" TP-1.00MM 69.622,17.793 r180 bottom
L1 "SRP4020TA-100M" SRP4020 40.166,9.653 r180 top value=10u
L2 "LQM18PN2R2MGHD" FP-LQM18PN_GH-IPC_C 8.775,47.532 r0 top value=2.2µH
L3 "MAKK2016T3R3M" MAKK2016T3R3M-Footprint-1 28.788,13.201 r0 top value=3.3µH
L4 "LQM18DH470M70L" L-0603 46.553,16.454 r180 top
LPO_IN "CMP-018-0005-A.3" TP-1.00MM 14.742,43.193 r180 bottom
PB1 "IT-1185AP1C-160G-GTR" C&K_PTS820_NO_HOLES-1 3,51.24 r0 top
PB2 "IT-1185AP1C-160G-GTR" C&K_PTS820_NO_HOLES-1 3,2.1 r0 top
PB12 "CMP-018-0005-A.3" TP-1.00MM 75.805,17.779 r180 bottom
PCLK "CMP-018-0005-A.3" TP-1.00MM 13.322,30.479 r180 bottom
POWER_EN "CMP-018-0005-A.3" TP-1.00MM 13.322,17.779 r180 bottom
PWDN "CMP-018-0005-A.3" TP-1.00MM 26.862,17.779 r180 bottom
PWR_LED "CMP-018-0005-A.3" TP-1.00MM 3.582,36.843 r180 bottom
R1 "CRCW0402976KFKED" RES-0402 8.275,34.7 r180 top value=976k
R2 "RC0402FR-075K1L" RES-0402 7.1,41.6 r270 top value=5.1k
R3 "CRCW0402100KFKEDC" RES-0402 33.746,22.698 r90 top value=100k
R4 "CRCW0402100KFKEDC" RES-0402 9.9,4.2 r0 top value=100k
R5 "CRCW04020000Z0EDC" RES-0402 40.526,36.328 r90 top value=0
R6 "CRCW04020000Z0EDC" RES-0402 36.2,19.375 r90 top value=0
R7 "CRCW0402330RJNED" RES-0402 45.8,18.865 r270 top value=330
R8 "CRCW04020000Z0EDC" RES-0402 36.675,18.9 r180 top value=0
R9 "CRCW04020000Z0EDC" RES-0402 18.619,43.785 r90 top value=0
R10 "CRCW0402330RJNED" RES-0402 8.6,33.1 r180 top value=330
R11 "CRCW0402330RJNED" RES-0402 9.9,1 r0 top value=330
R12 "CRCW0402330RJNED" RES-0402 9.9,2.1 r0 top value=330
R13 "CRCW0402330RJNED" RES-0402 9.9,3.2 r0 top value=330
R14 "CRCW04020000Z0EDC" RES-0402 6.236,46.564 r135 top value=0
R15 "CRCW0402976KFKED" RES-0402 27.382,11.479 r0 top value=976k
R16 "CRCW0402220KFKED" RES-0402 25.758,10.111 r90 top value=220k
R17 "RC0402FR-075K1L" RES-0402 8.1,41.6 r270 top value=5.1k
R18 "CRCW0402976KFKED" RES-0402 3.125,14.6 r0 top value=976k
R19 "RC0402FR-075K1L" RES-0402 29.235,40.898 r0 top value=5.1k
R20 "RC0402FR-075K1L" RES-0402 32.085,40.898 r180 top value=5.1k
R21 "CRCW0402100KFKEDC" RES-0402 69.621,14.16 r180 top value=100k
R22 "CRCW04020000Z0EDC" RES-0402 24.855,4.99 r180 top value=0
R23 "CRCW04020000Z0EDC" RES-0402 28.095,4.99 r180 top value=0
R24 "CRCW04020000Z0EDC" RES-0402 28.06,6.419 r180 top value=0
R25 "CRCW04020000Z0EDC" RES-0402 17.878,9.309 r270 top value=0
R26 "RC0402FR-075K1L" RES-0402 29.235,38.098 r0 top value=5.1k
R27 "RC0402FR-075K1L" RES-0402 29.235,39.498 r0 top value=5.1k
R28 "RC0402FR-075K1L" RES-0402 32.085,39.498 r0 top value=5.1k
R29 "RC0402FR-075K1L" RES-0402 32.085,38.098 r0 top value=5.1k
R30 "CRCW0402100KFKEDC" RES-0402 23.078,10.111 r270 top value=100k
R31 "CRCW0402100KFKEDC" RES-0402 45.667,8.575 r0 top value=100k
R32 "RC0402FR-075K1L" RES-0402 15.98,13.1 r90 top value=5.1k
R33 "CRCW040219K1FKEDC" RES-0402 48.842,8.1 r270 top value=19.1k
R34 "RC0402FR-075K1L" RES-0402 14.98,13.1 r90 top value=5.1k
R35 "CRCW040219K1FKEDC" RES-0402 48.831,13.072 r90 top value=19.1k
R36 "RC0402FR-075K1L" RES-0402 46.8,13.753 r180 top value=5.1k
R37 "RC0402FR-075K1L" RES-0402 13.98,13.1 r90 top value=5.1k
R38 "CRCW04020000Z0EDC" RES-0402 36.716,12.128 r270 top value=0
R39 "CRCW04020000Z0EDC" RES-0402 31.874,10.687 r270 top value=0
R40 "CRCW04020000Z0EDC" RES-0402 19.6,43.785 r90 top value=0
RED "CMP-018-0005-A.3" TP-1.00MM 6.122,2.553 r270 bottom
SCL4 "CMP-018-0005-A.3" TP-1.00MM 13.322,35.559 r180 bottom
SDATA "CMP-018-0005-A.3" TP-1.00MM 26.862,35.559 r180 bottom
SDIO_CLK "CMP-018-0005-A.3" TP-1.00MM 23.902,45.733 r180 bottom
SDIO_CMD "CMP-018-0005-A.3" TP-1.00MM 18.822,45.733 r180 bottom
SDIO_D0 "CMP-018-0005-A.3" TP-1.00MM 26.442,45.733 r180 bottom
SDIO_D1 "CMP-018-0005-A.3" TP-1.00MM 18.822,43.193 r180 bottom
SDIO_D2 "CMP-018-0005-A.3" TP-1.00MM 21.362,45.733 r180 bottom
SDIO_D3 "CMP-018-0005-A.3" TP-1.00MM 28.982,45.733 r180 bottom
U1 "STM32H747XIH6" STM32H747XIH6-Footprint-1 41.726,27.953 r0 top locked
U3 "AS4C4M16SA-6BIN" AS4C4M16SA-7BCN-Footprint-1 55.504,27.96 r180 top locked
U4 "ATECC608A-MAHDA-T" UDFN8 22.326,43.17 r270 top
U5 "LBEE5KL1DX-883" LBEE5KL1DX-883 13.915,44.975 r0 top locked
U6 "MP2322GQH" QFN50P150X200X90-8L 25.246,12.229 r0 top
U7 "AP63200WU-7" SOT95P280X100-6N 46.2,11.2 r180 top
U8 "AT25SF128A-MHB-T" PSON127P600X60_HS-9N 29.796,27.953 r270 top
U9 "SLG59H1341C" BGA9C40P3X3_121X121X62 13.1,15.3 r90 top
UART7_CTS "CMP-018-0005-A.3" TP-1.00MM 18.822,10.173 r180 bottom
UART7_RTS "CMP-018-0005-A.3" TP-1.00MM 16.282,10.173 r180 bottom
UART7_RX "CMP-018-0005-A.3" TP-1.00MM 21.362,40.653 r180 bottom
UART7_TX "CMP-018-0005-A.3" TP-1.00MM 16.282,12.713 r180 bottom
USB0_CC1 "CMP-018-0005-A.3" TP-1.00MM 6.122,40.653 r180 bottom
USB0_CC2 "CMP-018-0005-A.3" TP-1.00MM 3.582,40.653 r180 bottom
USB0_DN "CMP-018-0005-A.3" TP-1.00MM 9.163,37.809 r180 bottom
USB0_DP "CMP-018-0005-A.3" TP-1.00MM 9.163,40.349 r180 bottom
USB0_VBUS "CMP-018-0005-A.3" TP-1.00MM 6.122,36.843 r180 bottom
USB1_DN "CMP-018-0005-A.3" TP-1.00MM 44.221,39.463 r0 bottom
USB1_DP "CMP-018-0005-A.3" TP-1.00MM 44.221,36.923 r0 bottom
USB1_VBUS "CMP-018-0005-A.3" TP-1.00MM 13.742,12.713 r180 bottom
VSYNC "CMP-018-0005-A.3" TP-1.00MM 13.322,33.019 r180 bottom
WIFI_HWAKE "CMP-018-0005-A.3" TP-1.00MM 21.362,7.633 r180 bottom
WIFI_ON "CMP-018-0005-A.3" TP-1.00MM 21.362,43.193 r180 bottom
XCLK "CMP-018-0005-A.3" TP-1.00MM 26.862,30.479 r180 bottom
Y1 "SIT1532AI-J4-DCC-32.768E" SiT1532AI-J4-DCC-32.768E-Footprint-1 19.319,42.21 r180 top
Y2 "CM315D32768DZFT" ABS07 35.5,16.31 r0 top
Y3 "FTX16.000M12SM3S-30/30" CRYSTAL_3.2x2.5mm_16MHz 41.2,16.96 r0 top

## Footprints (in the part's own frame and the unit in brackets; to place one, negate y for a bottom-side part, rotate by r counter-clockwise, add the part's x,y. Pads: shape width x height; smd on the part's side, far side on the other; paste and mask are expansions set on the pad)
2X03 [mm]
  oct 1.501x1.501 / inner oct 1.524x1.524 / far side oct 1.501x1.501 hole 0.95: 1(2.54,1.27) 2(2.54,-1.27) 3(0,1.27) 4(0,-1.27) 5(-2.54,1.27) 6(-2.54,-1.27)
  body extent -3.81,-2.54 3.81,2.5, height 8.5
21TW-247 [mm]
  round 0 hole 1.1 unplated mask+0.2: 0(-11.43,-1.27) 0(-11.43,1.27) 0(-8.89,-1.27) 0(-8.89,1.27) 0(-6.35,-1.27) 0(-6.35,1.27) 0(-3.81,-1.27) 0(-3.81,1.27) 0(-1.27,1.27) 0(-1.27,-1.27) 0(1.27,1.27) 0(1.27,-1.27) 0(3.81,-1.27) 0(3.81,1.27) 0(6.35,-1.27) 0(6.35,1.27) 0(8.89,-1.27) 0(8.89,1.27) 0(11.43,-1.27) 0(11.43,1.27)
  round 0 hole 1.8 unplated paste-2539.97: 0(-10.16,0) 0(10.16,0)
  rrect25% 1.02x2.1 smd mask+0.1: 1(-11.43,-3.05)
  rrect50% 1.02x2.1 smd mask+0.1: 2(-11.43,3.05) 3(-8.89,-3.05) 4(-8.89,3.05) 5(-6.35,-3.05) 6(-6.35,3.05) 7(-3.81,-3.05) 8(-3.81,3.05) 9(-1.27,-3.05) 10(-1.27,3.05) 11(1.27,-3.05) 12(1.27,3.05) 13(3.81,-3.05) 14(3.81,3.05) 15(6.35,-3.05) 16(6.35,3.05) 17(8.89,-3.05) 18(8.89,3.05) 19(11.43,-3.05) 20(11.43,3.05)
  body extent -12.7,-3.29 12.7,3.29, height 3.71
21TW-291 [mm]
  round 0 hole 1.1 unplated mask+0.2: 0(-13.97,-1.27) 0(-13.97,1.27) 0(-11.43,-1.27) 0(-11.43,1.27) 0(-8.89,-1.27) 0(-8.89,1.27) 0(-6.35,-1.27) 0(-6.35,1.27) 0(-3.81,-1.27) 0(-3.81,1.27) 0(-1.27,1.27) 0(-1.27,-1.27) 0(1.27,1.27) 0(1.27,-1.27) 0(3.81,-1.27) 0(3.81,1.27) 0(6.35,-1.27) 0(6.35,1.27) 0(8.89,-1.27) 0(8.89,1.27) 0(11.43,-1.27) 0(11.43,1.27) 0(13.97,-1.27) 0(13.97,1.27)
  round 0 hole 1.8 unplated paste-2539.97: 0(-12.7,0) 0(12.7,0)
  rrect25% 1.02x2.1 smd mask+0.1: 1(-13.97,-3.05)
  rrect50% 1.02x2.1 smd mask+0.1: 2(-13.97,3.05) 3(-11.43,-3.05) 4(-11.43,3.05) 5(-8.89,-3.05) 6(-8.89,3.05) 7(-6.35,-3.05) 8(-6.35,3.05) 9(-3.81,-3.05) 10(-3.81,3.05) 11(-1.27,-3.05) 12(-1.27,3.05) 13(1.27,-3.05) 14(1.27,3.05) 15(3.81,-3.05) 16(3.81,3.05) 17(6.35,-3.05) 18(6.35,3.05) 19(8.89,-3.05) 20(8.89,3.05) 21(11.43,-3.05) 22(11.43,3.05) 23(13.97,-3.05) 24(13.97,3.05)
  body extent -15.27,-3.29 15.21,3.29, height 3.71
22TW-258-Footprint-1 [mm]
  oval 1.4x2.1 hole 0.8 slot 1.5 at 90 deg paste-2539.97 mask+0.2: 1(6.15,0)
  oval 2.1x1.4 hole 0.8 slot 1.5 at 0 deg paste-2539.97 mask+0.2: 2(5.35,2.85) 3(5.35,-2.85) 4(-2.65,-3.3) 4(-2.65,3.3)
  round 1 hole 1.2 unplated paste-2539.97 mask+0.3: NC1(-4.15,0) NC2(2.85,0)
  body extent -8.43,-3.5 6.15,3.5, height 6
ABS07 [mm]
  rrect50% 1.1x1.9 smd: 1(-1.25,0) 2(1.25,0)
  body extent -1.65,-0.83 1.65,0.83, height 0.9
AS4C4M16SA-7BCN-Footprint-1 [mm]
  round 0.41 smd mask+0.05: A1(-3.2,-3.2) A2(-3.2,-2.4) A3(-3.2,-1.6) A7(-3.2,1.6) A8(-3.2,2.4) A9(-3.2,3.2) B1(-2.4,-3.2) B2(-2.4,-2.4) B3(-2.4,-1.6) B7(-2.4,1.6) B8(-2.4,2.4) B9(-2.4,3.2) C1(-1.6,-3.2) C2(-1.6,-2.4) C3(-1.6,-1.6) C7(-1.6,1.6) C8(-1.6,2.4) C9(-1.6,3.2) D1(-0.8,-3.2) D2(-0.8,-2.4) D3(-0.8,-1.6) D7(-0.8,1.6) D8(-0.8,2.4) D9(-0.8,3.2) E1(0,-3.2) E2(0,-2.4) E3(0,-1.6) E7(0,1.6) E8(0,2.4) E9(0,3.2) F1(0.8,-3.2) F2(0.8,-2.4) F3(0.8,-1.6) F7(0.8,1.6) F8(0.8,2.4) F9(0.8,3.2) G1(1.6,-3.2) G2(1.6,-2.4) G3(1.6,-1.6) G7(1.6,1.6) G8(1.6,2.4) G9(1.6,3.2) H1(2.4,-3.2) H2(2.4,-2.4) H3(2.4,-1.6) H7(2.4,1.6) H8(2.4,2.4) H9(2.4,3.2) J1(3.2,-3.2) J2(3.2,-2.4) J3(3.2,-1.6) J7(3.2,1.6) J8(3.2,2.4) J9(3.2,3.2)
  silkscreen extent -4.31,-4.31 -4.21,-4.21, body extent -4,-4 4,4, height 1.15
BGA9C40P3X3_121X121X62 [mm] "BGA, 9-Leads, Body 1,21x1,21mmx0,63mm, Pitch 0,40mm"
  round 0.25 smd mask+0.05: A1(-0.4,0.4) A2(0,0.4) A3(0.4,0.4) B1(-0.4,0) B2(0,0) B3(0.4,0) C1(-0.4,-0.4) C2(0,-0.4) C3(0.4,-0.4)
  silkscreen extent -0.76,0.66 -0.66,0.76, body extent -0.61,-0.61 0.61,0.61, height 0.63
C&K_PTS820_NO_HOLES-1 [mm]
  rrect49% 1x1.6 smd mask+0.05: 1(-2.1,0) 2(2.1,0)
  body extent -2.25,-1.45 2.25,1.45, height 2
CAP-0402#1 [mm] "Chip Capacitor, 2-Leads, Body  0402 (in) 1005 (mm), IPC Medium Density"
  rrect52% 0.63x0.58 smd mask+0.05: 1(-0.435,0) 2(0.435,0)
  body extent -0.5,-0.25 0.5,0.25, height 0.5
CAP-0402#2 [mm] "Chip Capacitor, 2-Leads, Body  0402 (in) 1005 (mm), IPC Medium Density"
  rrect52% 0.63x0.58 smd mask+0: 1(-0.435,0) 2(0.435,0)
  body extent -0.5,-0.25 0.5,0.25, height 0.5
CAP-0603 [mm] "Chip Capacitor, Body 0603 imperial,1.6x0.8mm, IPC High Density"
  rrect51% 0.87x0.97 smd mask+0.05: 1(-0.75,0) 2(0.75,0)
  body extent -0.8,-0.4 0.8,0.4, height 0.8
CAP-0805 [mm] "Chip Capacitor, Body 0805 imperial, 2.0x1.2mm, IPC Medium Density"
  rrect45% 1.11x1.47 smd mask+0.05: 1(-0.85,0) 2(0.85,0)
  body extent -1,-0.62 1,0.63, height 1.25
CRYSTAL_3.2x2.5mm_16MHz [mm]
  rrect10% 1.3x1.05 smd: 1(-1.15,-0.925) 2(1.15,-0.925) 3(1.15,0.925) 4(-1.15,0.925)
  body extent -1.6,-1.25 1.6,1.25, height 0.8
CX90B-16P-Footprint-1 [mm]
  rect 0.57x0.85 smd mask+0.05: A1(-3.635,1.988) A12(3.635,1.988)
  rect 0.25x0.85 smd mask+0.05: A4(-2.275,1.988) A9(2.275,1.988) B1(3.025,1.988) B4(1.825,1.988) B9(-1.825,1.988) B12(-3.025,1.988)
  rect 0.2x0.85 smd mask+0.05: A5(-1.4,1.988) A6(-0.6,1.988) A7(0.6,1.988) A8(1.4,1.988) B5(1,1.988) B6(0.2,1.988) B7(-0.2,1.988) B8(-1,1.988)
  round 0.2 hole 0.45 unplated paste-2539.97 mask+0.2: FIXING(-3.32,0.988) FIXING(3.32,0.988)
  rect 1.71x2.6 smd paste-0.3 mask+0.05: FIXING(-1.565,-1.837) FIXING(1.565,-1.837)
  oval 1.05x2.6 hole 0.6 slot 2 at 90 deg copper offset -0.025,0 mask+0.05: SHIELD1(-4.62,1.563)
  oval 1.05x2.6 hole 0.6 slot 2 at 90 deg copper offset 0.025,0 mask+0.05: SHIELD2(4.62,1.563)
  oval 1.2x2.3 hole 0.6 slot 1.7 at 90 deg mask+0.05: SHIELD3(-4.42,-1.987) SHIELD4(4.42,-1.987)
  body extent -4.77,-4.4 4.77,2.4, height 3.17
"Fiducial mark 1mm-Footprint-1" [mm]
  round 1 smd paste-10 mask+0.5: 1(0,0)
  Top Layer keep-out circle w1: c0,0 r0.5
FP-LQM18PN_GH-IPC_C [mm]
  rrect50% 0.7x0.7 smd: 1(-0.7,0) 2(0.7,0)
  body extent -0.8,-0.4 0.8,0.4, height 1
FTSH-105-01-F-DV-Footprint-1 [mm]
  rect 0.76x2.3 smd: 1(-2.54,-1.95) 2(-2.54,1.95) 3(-1.27,-1.95) 4(-1.27,1.95) 5(0,-1.95) 6(0,1.95) 7(1.27,-1.95) 8(1.27,1.95) 9(2.54,-1.95) 10(2.54,1.95)
  silkscreen extent -2.59,-3.66 -2.49,-3.56, body extent -3.17,-2.92 3.17,2.92, height 5.98
"GIGA custom header side-Footprint-1" [mm]
  round 1.7 hole 1 mask+0.2: 1(-1.27,21.59) 2(1.27,21.59) 3(-1.27,19.05) 4(1.27,19.05) 5(-1.27,16.51) 6(1.27,16.51) 7(-1.27,13.97) 8(1.27,13.97) 9(-1.27,11.43) 10(1.27,11.43) 11(-1.27,8.89) 12(1.27,8.89) 13(-1.27,6.35) 14(1.27,6.35) 15(-1.27,3.81) 16(1.27,3.81) 17(-1.27,1.27) 18(1.27,1.27) 19(-1.27,-1.27) 20(1.27,-1.27) 21(-1.27,-3.81) 22(1.27,-3.81) 23(-1.27,-6.35) 24(1.27,-6.35) 25(-1.27,-8.89) 26(1.27,-8.89) 27(-1.27,-11.43) 28(1.27,-11.43) 29(-1.27,-13.97) 30(1.27,-13.97) 31(-1.27,-16.51) 32(1.27,-16.51) 33(-1.27,-19.05) 34(1.27,-19.05) 35(-1.27,-21.59) 36(1.27,-21.59)
  body extent -2.5,-22.9 2.5,23.32, height 8.52
"GIGA header custom analog" [mm]
  round 1.7 hole 1 mask+0.2: 1(-30.48,0) 2(-27.94,0) 3(-25.4,0) 4(-22.86,0) 5(-20.32,0) 6(-17.78,0) 7(-15.24,0) 8(-12.7,0) 9(-7.62,0) 10(-5.08,0) 11(-2.54,0) 12(0,0) 13(2.54,0) 14(5.08,0) 15(7.62,0) 16(10.16,0) 17(15.24,0) 18(17.78,0) 19(20.32,0) 20(22.86,0) 21(25.4,0) 22(27.94,0) 23(30.48,0) 24(33.02,0)
  body extent -32.1,-1.25 34.54,1.25, height 8.51
"GIGA Header custom digital" [mm]
  round 1.7 hole 1 mask+0.2: 1(-34.544,0) 2(-32.004,0) 3(-29.464,0) 4(-26.924,0) 5(-24.384,0) 6(-21.844,0) 7(-19.304,0) 8(-16.764,0) 9(-14.224,0) 10(-11.684,0) 11(-7.62,0) 12(-5.08,0) 13(-2.54,0) 14(0,0) 15(2.54,0) 16(5.08,0) 17(7.62,0) 18(10.16,0) 19(15.24,0) 20(17.78,0) 21(20.32,0) 22(22.86,0) 23(25.4,0) 24(27.94,0) 25(30.48,0) 26(33.02,0)
  body extent -36.09,-1.25 34.51,1.25, height 8.52
L-0603 [mm] "Chip Inductor - Body 0603 imperial,1.6x0.8mm, IPC High Density"
  rrect51% 0.75x0.87 smd mask+0: 1(-0.71,0) 2(0.71,0)
  body extent -0.8,-0.4 0.8,0.4, height 0.8
LBEE5KL1DX-883 [mm]
  rrect50% 0.28x0.64 smd mask+0.05: 1(-2.25,-2.015) 2(-1.8,-2.015) 3(-1.35,-2.015) 4(-0.9,-2.015) 5(-0.45,-2.015) 6(0,-2.015) 7(0.45,-2.015) 8(0.9,-2.015) 9(1.35,-2.015) 10(1.8,-2.015) 11(2.25,-2.015) 22(2.25,2.015) 23(1.8,2.015) 24(1.35,2.015) 25(0.9,2.015) 26(0.45,2.015) 27(0,2.015) 28(-0.45,2.015) 29(-0.9,2.015) 30(-1.35,2.015) 31(-1.8,2.015) 32(-2.25,2.015)
  rrect50% 0.64x0.4 smd mask+0.05: 12(2.915,-2.087) 21(2.915,2.087) 33(-2.915,2.087) 42(-2.915,-2.087)
  rrect50% 0.64x0.28 smd mask+0.05: 13(2.915,-1.575) 14(2.915,-1.125) 15(2.915,-0.675) 16(2.915,-0.225) 17(2.915,0.225) 18(2.915,0.675) 19(2.915,1.125) 20(2.915,1.575) 34(-2.915,1.575) 35(-2.915,1.125) 36(-2.915,0.675) 37(-2.915,0.225) 38(-2.915,-0.225) 39(-2.915,-0.675) 40(-2.915,-1.125) 41(-2.915,-1.575)
  round 0.2 smd paste+0 mask+0.05: 43(-1,-0.75)
  rrect10% 1x1 smd mask+0.05: 44(1,-0.75) 45(-1,0.75) 46(1,0.75)
  Top Layer region: -1.485,-0.765 -1.496,-0.748 -1.5,-0.729 -1.5,-0.729 -1.5,-0.3 -1.496,-0.281 -1.485,-0.265 -1.469,-0.254 -1.45,-0.25 -1.45,-0.25 -0.55,-0.25 -0.531,-0.254 -0.515,-0.265 -0.504,-0.281 -0.5,-0.3 -0.5,-0.3 -0.5,-1.2 -0.504,-1.219 -0.515,-1.235 -0.531,-1.246 -0.55,-1.25 -0.55,-1.25 -0.979,-1.25 -0.998,-1.246 -1.015,-1.235 -1.015,-1.235
  silkscreen extent -3.56,-2.67 -3.46,-2.57, body extent -3.47,-2.57 3.48,2.58, height 1.1
LEDC1608X80N-AK [mm]
  rrect50% 0.72x0.87 smd: A(0.725,0) C(-0.725,0)
  body extent -0.8,-0.4 0.8,0.4, height 0.79
MAKK2016T3R3M-Footprint-1 [mm]
  rect 0.7x1.8 smd mask+0.05: 1(-0.75,0) 2(0.75,0)
  body extent -1,-0.8 1,0.8, height 1
"PIN HEADER 2.54mm VERT. 1x3POS" [mm]
  round 1.7 hole 1 mask+0.2: 1(-2.54,0) 2(0,0) 3(2.54,0)
PSON127P600X60_HS-9N [mm] "PSON, 8-Leads, Body 5,00x6,00mm, Pitch 1,27mm, Thermal Pad 4,00x3,40mm, IPC Medium Density"
  rect 0.8x0.5 smd mask+0.05: 1(-2.67,1.905) 2(-2.67,0.635) 3(-2.67,-0.635) 4(-2.67,-1.905) 5(2.67,-1.905) 6(2.67,-0.635) 7(2.67,0.635) 8(2.67,1.905)
  rect 3.4x4 smd paste-10 mask+0.05: 9(0,0)
  silkscreen extent -3.22,2.62 -3.13,2.72, body extent -3.05,-2.55 3.05,2.55, height 0.6
QFN50P150X200X90-8L [mm] "QFN, 8-Leads, Body 1,50x2,00mm, Pitch 0,50mm, IPC High Density"
  round 0.025 smd mask+0.05: 1(-0.7,0.75)
  rrect25% 0.7x0.25 smd mask+0.05: 2(-0.7,0.25) 3(-0.7,-0.25) 4(-0.7,-0.75) 5(0.7,-0.75) 6(0.7,-0.25) 7(0.7,0.25) 8(0.7,0.75)
  Top Layer region: -1.044,0.625 -1.056,0.627 -1.066,0.634 -1.073,0.644 -1.075,0.656 -1.075,0.656 -1.075,0.844 -1.073,0.856 -1.066,0.866 -1.056,0.873 -1.044,0.875 -1.044,0.875 -0.452,0.875 -0.325,0.748 -0.325,0.656 -0.327,0.644 -0.334,0.634 -0.344,0.627 -0.356,0.625 -0.356,0.625
  silkscreen extent -1.07,1.14 -0.97,1.24, body extent -0.8,-1.05 0.8,1.05, height 0.9
RES-0402 [mm] "Chip Resistor, 2-Leads, Body  0402 (in) 1005 (mm), IPC Medium Density"
  rrect51% 0.55x0.58 smd mask+0.05: 1(-0.475,0) 2(0.475,0)
  body extent -0.5,-0.25 0.5,0.25, height 0.34
SiT1532AI-J4-DCC-32.768E-Footprint-1 [mm]
  round 0.25 smd mask+0.02: 1(-0.5,-0.205) 2(0.5,-0.205) 3(0.5,0.205) 4(-0.5,0.205)
  body extent -0.77,-0.42 0.77,0.42, height 0.55
SOD123-1 [mm]
  rrect50% 0.91x1.22 smd: A(1.635,0) C(-1.635,0)
  silkscreen extent -0.6,-0.6 0.6,0.6, body extent -1.85,-1 1.85,1, height 1.2
SOT95P280X100-6N [mm] "SOT23, 6-Leads, Body 2,90x2,80mm, Pitch 0,95mm, IPC Medium Density"
  rrect50% 1x0.55 smd mask+0.05: 1(-1.35,0.95) 2(-1.35,0) 3(-1.35,-0.95) 4(1.35,-0.95) 5(1.35,0) 6(1.35,0.95)
  silkscreen extent -1.29,1.58 -1.19,1.68, body extent -1.4,-1.5 1.4,1.5, height 1
SOT190P230X110-4N [mm]
  rrect33% 1.01x0.91 smd paste+0 mask+0.05: 1(-0.75,-0.955)
  rrect49% 0.61x0.91 smd paste+0 mask+0.05: 2(0.95,-0.955) 3(0.95,0.955) 4(-0.95,0.955)
  silkscreen extent -1.73,-1.03 -1.63,-0.93, body extent -1.45,-1.15 1.45,1.15, height 1
SRP4020 [mm]
  rect 1.5x2.4 smd: 1(-1.85,0) 2(1.85,0)
  body extent -2.15,-2 2.15,2, height 1.9
STM32H747XIH6-Footprint-1 [mm]
  round 0.37 smd: A1(-6.4,-6.4) A2(-6.4,-5.6) A3(-6.4,-4.8) A4(-6.4,-4) A5(-6.4,-3.2) A6(-6.4,-2.4) A7(-6.4,-1.6) A8(-6.4,-0.8) A9(-6.4,0) A10(-6.4,0.8) A11(-6.4,1.6) A12(-6.4,2.4) A13(-6.4,3.2) A14(-6.4,4) A15(-6.4,4.8) A16(-6.4,5.6) A17(-6.4,6.4) B1(-5.6,-6.4) B2(-5.6,-5.6) B3(-5.6,-4.8) B4(-5.6,-4) B5(-5.6,-3.2) B6(-5.6,-2.4) B7(-5.6,-1.6) B8(-5.6,-0.8) B9(-5.6,0) B10(-5.6,0.8) B11(-5.6,1.6) B12(-5.6,2.4) B13(-5.6,3.2) B14(-5.6,4) B15(-5.6,4.8) B16(-5.6,5.6) B17(-5.6,6.4) C1(-4.8,-6.4) C2(-4.8,-5.6) C3(-4.8,-4.8) C4(-4.8,-4) C5(-4.8,-3.2) C6(-4.8,-2.4) C7(-4.8,-1.6) C8(-4.8,-0.8) C9(-4.8,0) C10(-4.8,0.8) C11(-4.8,1.6) C12(-4.8,2.4) C13(-4.8,3.2) C14(-4.8,4) C15(-4.8,4.8) C16(-4.8,5.6) C17(-4.8,6.4) D1(-4,-6.4) D2(-4,-5.6) D3(-4,-4.8) D4(-4,-4) D5(-4,-3.2) D6(-4,-2.4) D7(-4,-1.6) D8(-4,-0.8) D9(-4,0) D10(-4,0.8) D11(-4,1.6) D12(-4,2.4) D13(-4,3.2) D14(-4,4) D15(-4,4.8) D16(-4,5.6) D17(-4,6.4) E1(-3.2,-6.4) E2(-3.2,-5.6) E3(-3.2,-4.8) E4(-3.2,-4) E5(-3.2,-3.2) E6(-3.2,-2.4) E7(-3.2,-1.6) E8(-3.2,-0.8) E9(-3.2,0) E10(-3.2,0.8) E11(-3.2,1.6) E12(-3.2,2.4) E13(-3.2,3.2) E14(-3.2,4) E15(-3.2,4.8) E16(-3.2,5.6) E17(-3.2,6.4) F1(-2.4,-6.4) F2(-2.4,-5.6) F3(-2.4,-4.8) F4(-2.4,-4) F5(-2.4,-3.2) F13(-2.4,3.2) F14(-2.4,4) F15(-2.4,4.8) F16(-2.4,5.6) F17(-2.4,6.4) G1(-1.6,-6.4) G2(-1.6,-5.6) G3(-1.6,-4.8) G4(-1.6,-4) G5(-1.6,-3.2) G7(-1.6,-1.6) G8(-1.6,-0.8) G9(-1.6,0) G10(-1.6,0.8) G11(-1.6,1.6) G13(-1.6,3.2) G14(-1.6,4) G15(-1.6,4.8) G16(-1.6,5.6) G17(-1.6,6.4) H1(-0.8,-6.4) H2(-0.8,-5.6) H3(-0.8,-4.8) H4(-0.8,-4) H5(-0.8,-3.2) H7(-0.8,-1.6) H8(-0.8,-0.8) H9(-0.8,0) H10(-0.8,0.8) H11(-0.8,1.6) H13(-0.8,3.2) H14(-0.8,4) H15(-0.8,4.8) H16(-0.8,5.6) H17(-0.8,6.4) J1(0,-6.4) J2(0,-5.6) J3(0,-4.8) J4(0,-4) J5(0,-3.2) J7(0,-1.6) J8(0,-0.8) J9(0,0) J10(0,0.8) J11(0,1.6) J13(0,3.2) J14(0,4) J15(0,4.8) J16(0,5.6) J17(0,6.4) K1(0.8,-6.4) K2(0.8,-5.6) K3(0.8,-4.8) K4(0.8,-4) K5(0.8,-3.2) K7(0.8,-1.6) K8(0.8,-0.8) K9(0.8,0) K10(0.8,0.8) K11(0.8,1.6) K13(0.8,3.2) K14(0.8,4) K15(0.8,4.8) K16(0.8,5.6) K17(0.8,6.4) L1(1.6,-6.4) L2(1.6,-5.6) L3(1.6,-4.8) L4(1.6,-4) L5(1.6,-3.2) L7(1.6,-1.6) L8(1.6,-0.8) L9(1.6,0) L10(1.6,0.8) L11(1.6,1.6) L13(1.6,3.2) L14(1.6,4) L15(1.6,4.8) L16(1.6,5.6) L17(1.6,6.4) M1(2.4,-6.4) M2(2.4,-5.6) M3(2.4,-4.8) M4(2.4,-4) M5(2.4,-3.2) M13(2.4,3.2) M14(2.4,4) M15(2.4,4.8) M16(2.4,5.6) M17(2.4,6.4) N1(3.2,-6.4) N2(3.2,-5.6) N3(3.2,-4.8) N4(3.2,-4) N5(3.2,-3.2) N6(3.2,-2.4) N7(3.2,-1.6) N8(3.2,-0.8) N9(3.2,0) N10(3.2,0.8) N11(3.2,1.6) N12(3.2,2.4) N13(3.2,3.2) N14(3.2,4) N15(3.2,4.8) N16(3.2,5.6) N17(3.2,6.4) P1(4,-6.4) P2(4,-5.6) P3(4,-4.8) P4(4,-4) P5(4,-3.2) P6(4,-2.4) P7(4,-1.6) P8(4,-0.8) P9(4,0) P10(4,0.8) P11(4,1.6) P12(4,2.4) P13(4,3.2) P14(4,4) P15(4,4.8) P16(4,5.6) P17(4,6.4) R1(4.8,-6.4) R2(4.8,-5.6) R3(4.8,-4.8) R4(4.8,-4) R5(4.8,-3.2) R6(4.8,-2.4) R7(4.8,-1.6) R8(4.8,-0.8) R9(4.8,0) R10(4.8,0.8) R11(4.8,1.6) R12(4.8,2.4) R13(4.8,3.2) R14(4.8,4) R15(4.8,4.8) R16(4.8,5.6) R17(4.8,6.4) T1(5.6,-6.4) T2(5.6,-5.6) T3(5.6,-4.8) T4(5.6,-4) T5(5.6,-3.2) T6(5.6,-2.4) T7(5.6,-1.6) T8(5.6,-0.8) T9(5.6,0) T10(5.6,0.8) T11(5.6,1.6) T12(5.6,2.4) T13(5.6,3.2) T14(5.6,4) T15(5.6,4.8) T16(5.6,5.6) T17(5.6,6.4) U1(6.4,-6.4) U2(6.4,-5.6) U3(6.4,-4.8) U4(6.4,-4) U5(6.4,-3.2) U6(6.4,-2.4) U7(6.4,-1.6) U8(6.4,-0.8) U9(6.4,0) U10(6.4,0.8) U11(6.4,1.6) U12(6.4,2.4) U13(6.4,3.2) U14(6.4,4) U15(6.4,4.8) U16(6.4,5.6) U17(6.4,6.4)
  silkscreen extent -7.16,-7.16 -7.06,-7.06, body extent -7,-7 7,7, height 1.06
TP-1.00MM [mm]
  rrect100% 1x1 smd paste-2.54: X(0,0)
U.FL-R-SMT-1(60)-1 [mm]
  rect 1.05x2.2 smd paste+0: GND(-1.475,0) GND(1.475,0)
  rect 1.05x1 smd paste+0: SIG(0,-1.6)
  body extent -1.5,-1.55 1.5,1.55, height 1.25
UDFN8 [mm] "QFN, 8-Leads, Body 3.00x2.00mm, Pitch 0.50mm, Thermal Pad 1.30x1.50mm, IPC Medium Density"
  rrect54% 0.26x0.64 smd paste+0 mask+0.05: 1(-0.75,-1.345) 2(-0.25,-1.345) 3(0.25,-1.345) 4(0.75,-1.345) 5(0.75,1.345) 6(0.25,1.345) 7(-0.25,1.345) 8(-0.75,1.345)
  rrect8% 1.5x1.3 smd paste-1.5 mask+0.05: 9(0,0)
  silkscreen extent -1.19,-1.83 -1.09,-1.73, body extent -1,-1.5 1,1.5, height 0.55
UHD1110-FKA-CL1A13R3Q1BBQFMF3 [mm]
  rrect25% 0.54x0.54 smd mask+0.05: 1(-0.395,-0.395) 2(0.395,-0.395) 3(0.395,0.395)
  round 0.025 smd mask+0.05: 4(-0.395,0.395)
  Top Layer region: -0.35,0.665 -0.125,0.44 -0.125,0.265 -0.136,0.212 -0.166,0.166 -0.212,0.136 -0.265,0.125 -0.265,0.125 -0.525,0.125 -0.578,0.136 -0.624,0.166 -0.654,0.212 -0.665,0.265 -0.665,0.265 -0.665,0.525 -0.654,0.578 -0.624,0.624 -0.578,0.654 -0.525,0.665 -0.525,0.665
  body extent -0.5,-0.5 0.5,0.5, height 0.63
USB-A-S-RA-CS11-SMT-HF-TR [mm]
  rrect25% 1.45x3 smd paste+0 mask+0.05: 1(-3.5,6) 2(-1,6) 3(1,6) 4(3.5,6)
  oval 1.8x3 hole 0.8 slot 1.6 at 90 deg paste-2539.97 mask+0.05: SHIELD1(-6.525,3.5) SHIELD2(6.525,3.5)
  oval 1.8x4 hole 0.8 slot 2.8 at 90 deg copper offset 0,0.2 paste-2539.97 mask+0.05: SHIELD3(-7.025,-3.4) SHIELD4(7.025,-3.4)
  body extent -7.25,-8.25 7.25,6.42, height 7.72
